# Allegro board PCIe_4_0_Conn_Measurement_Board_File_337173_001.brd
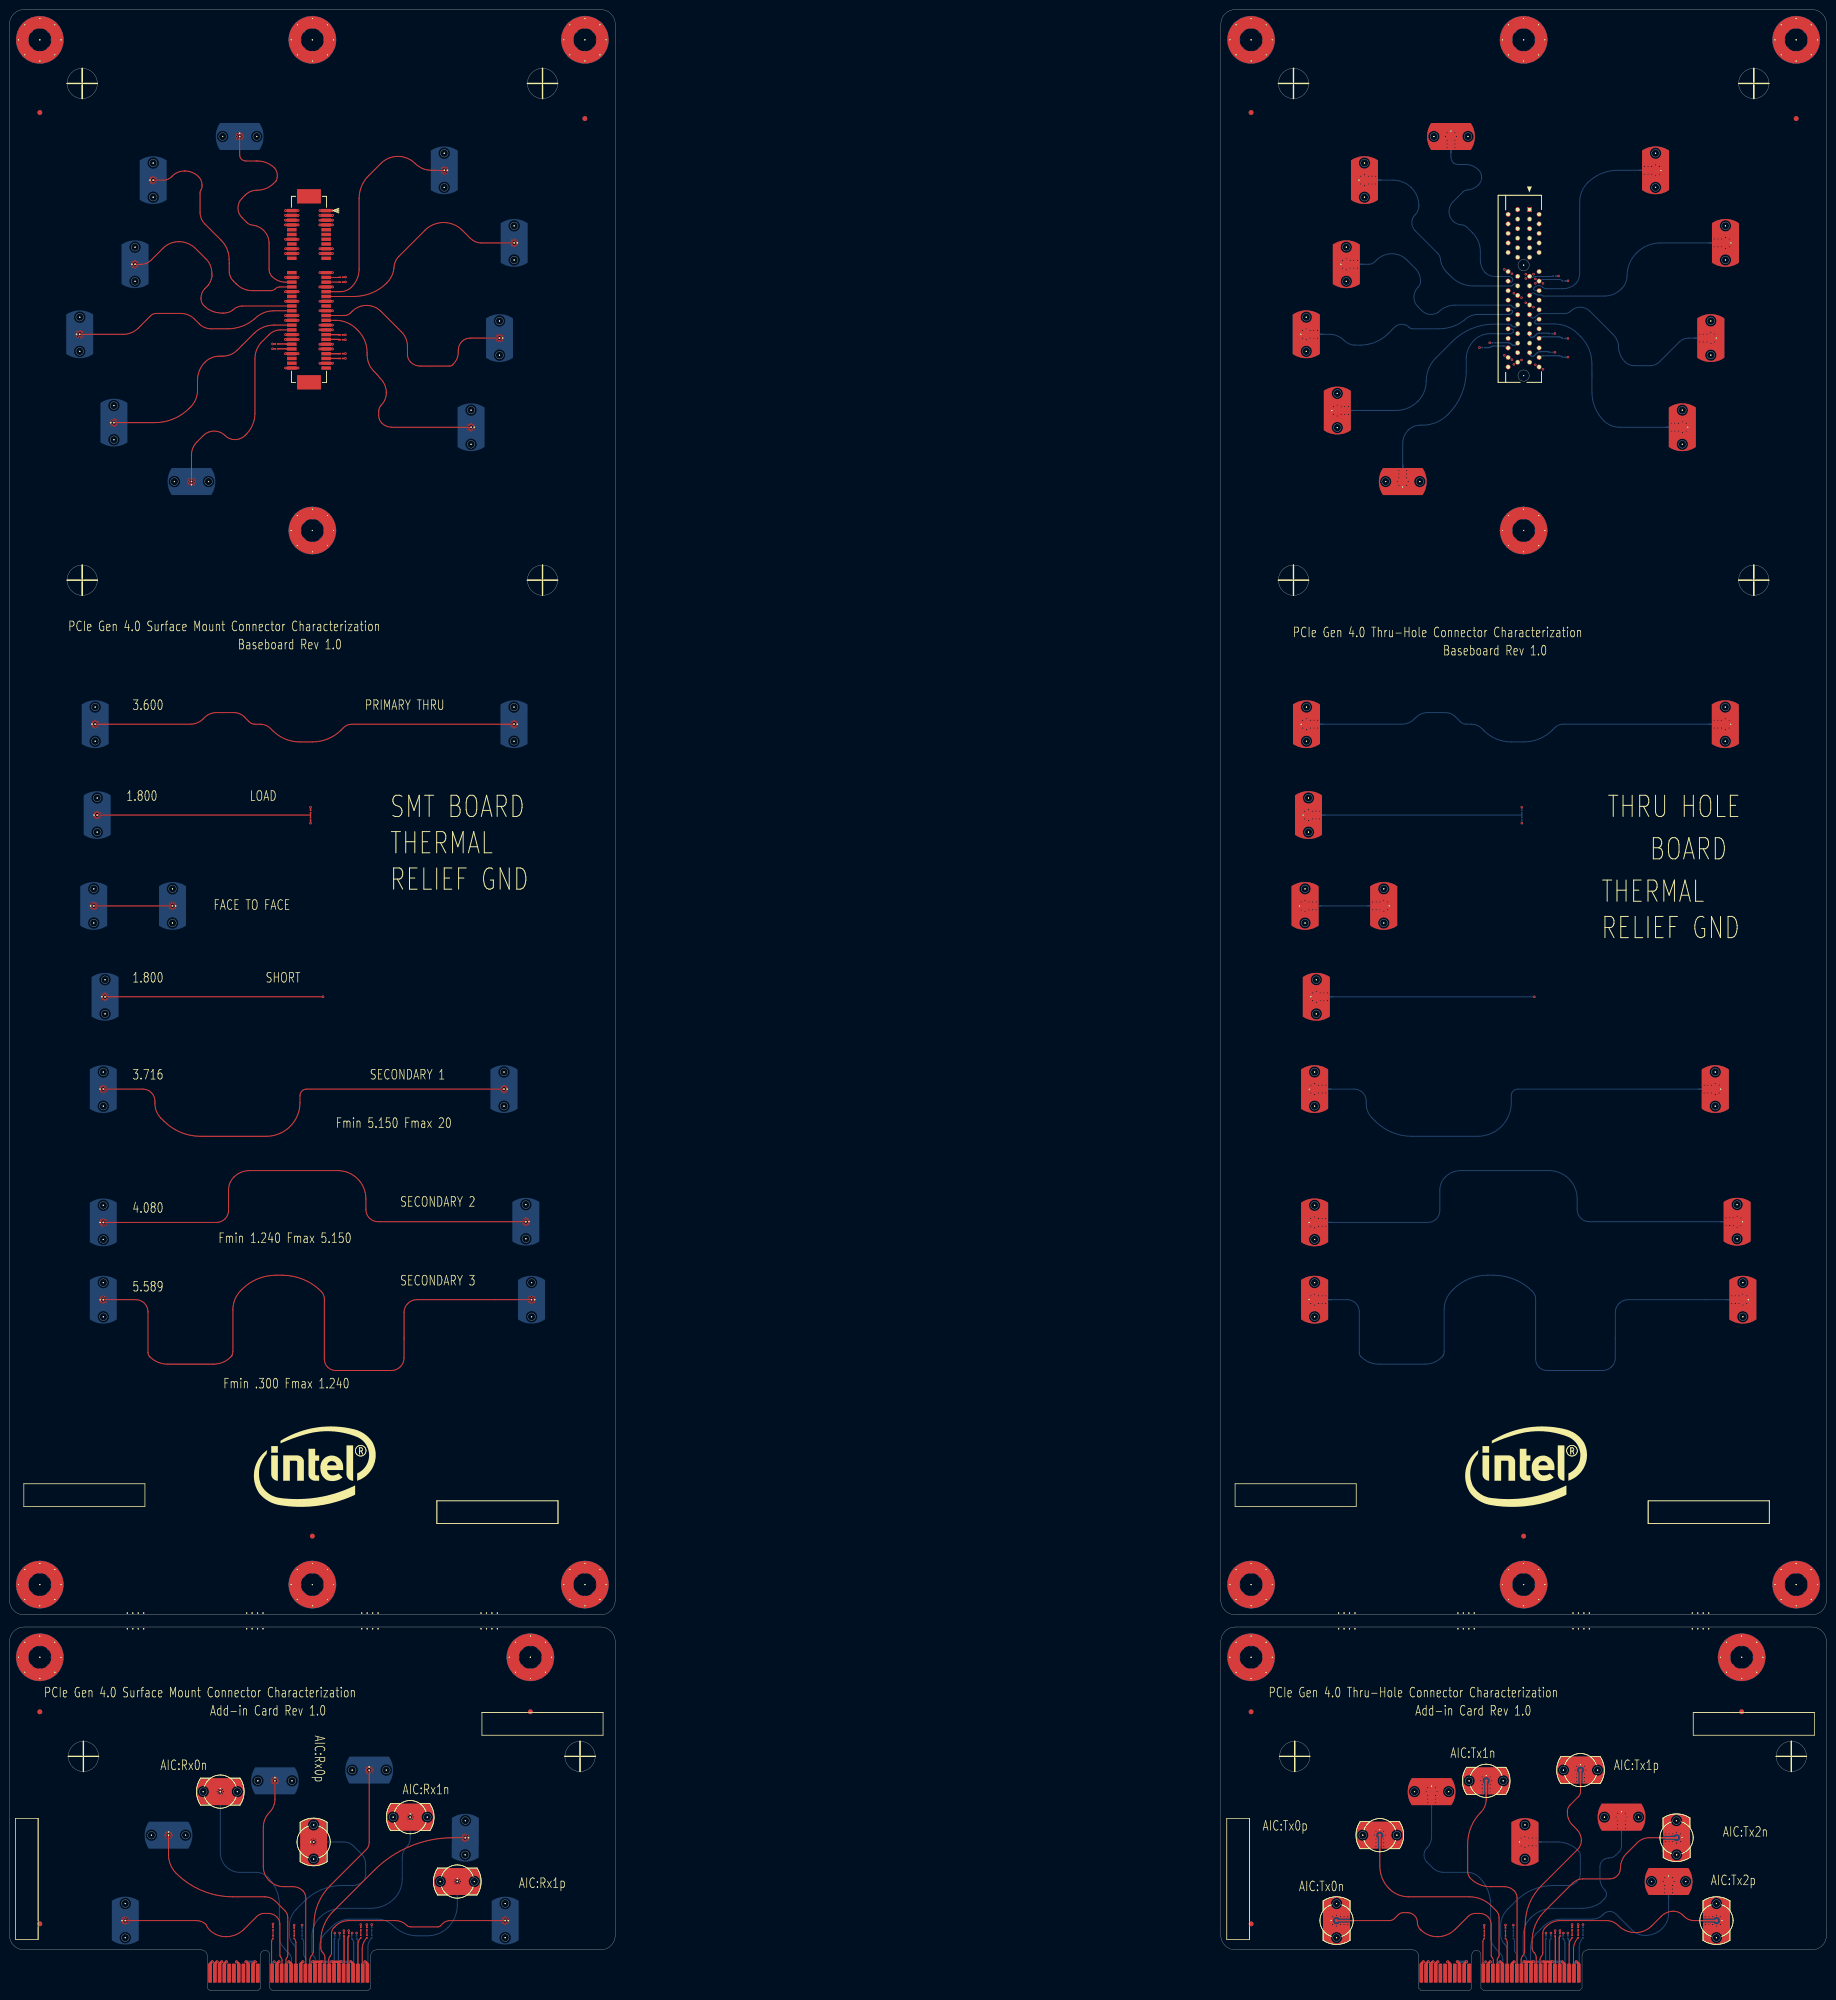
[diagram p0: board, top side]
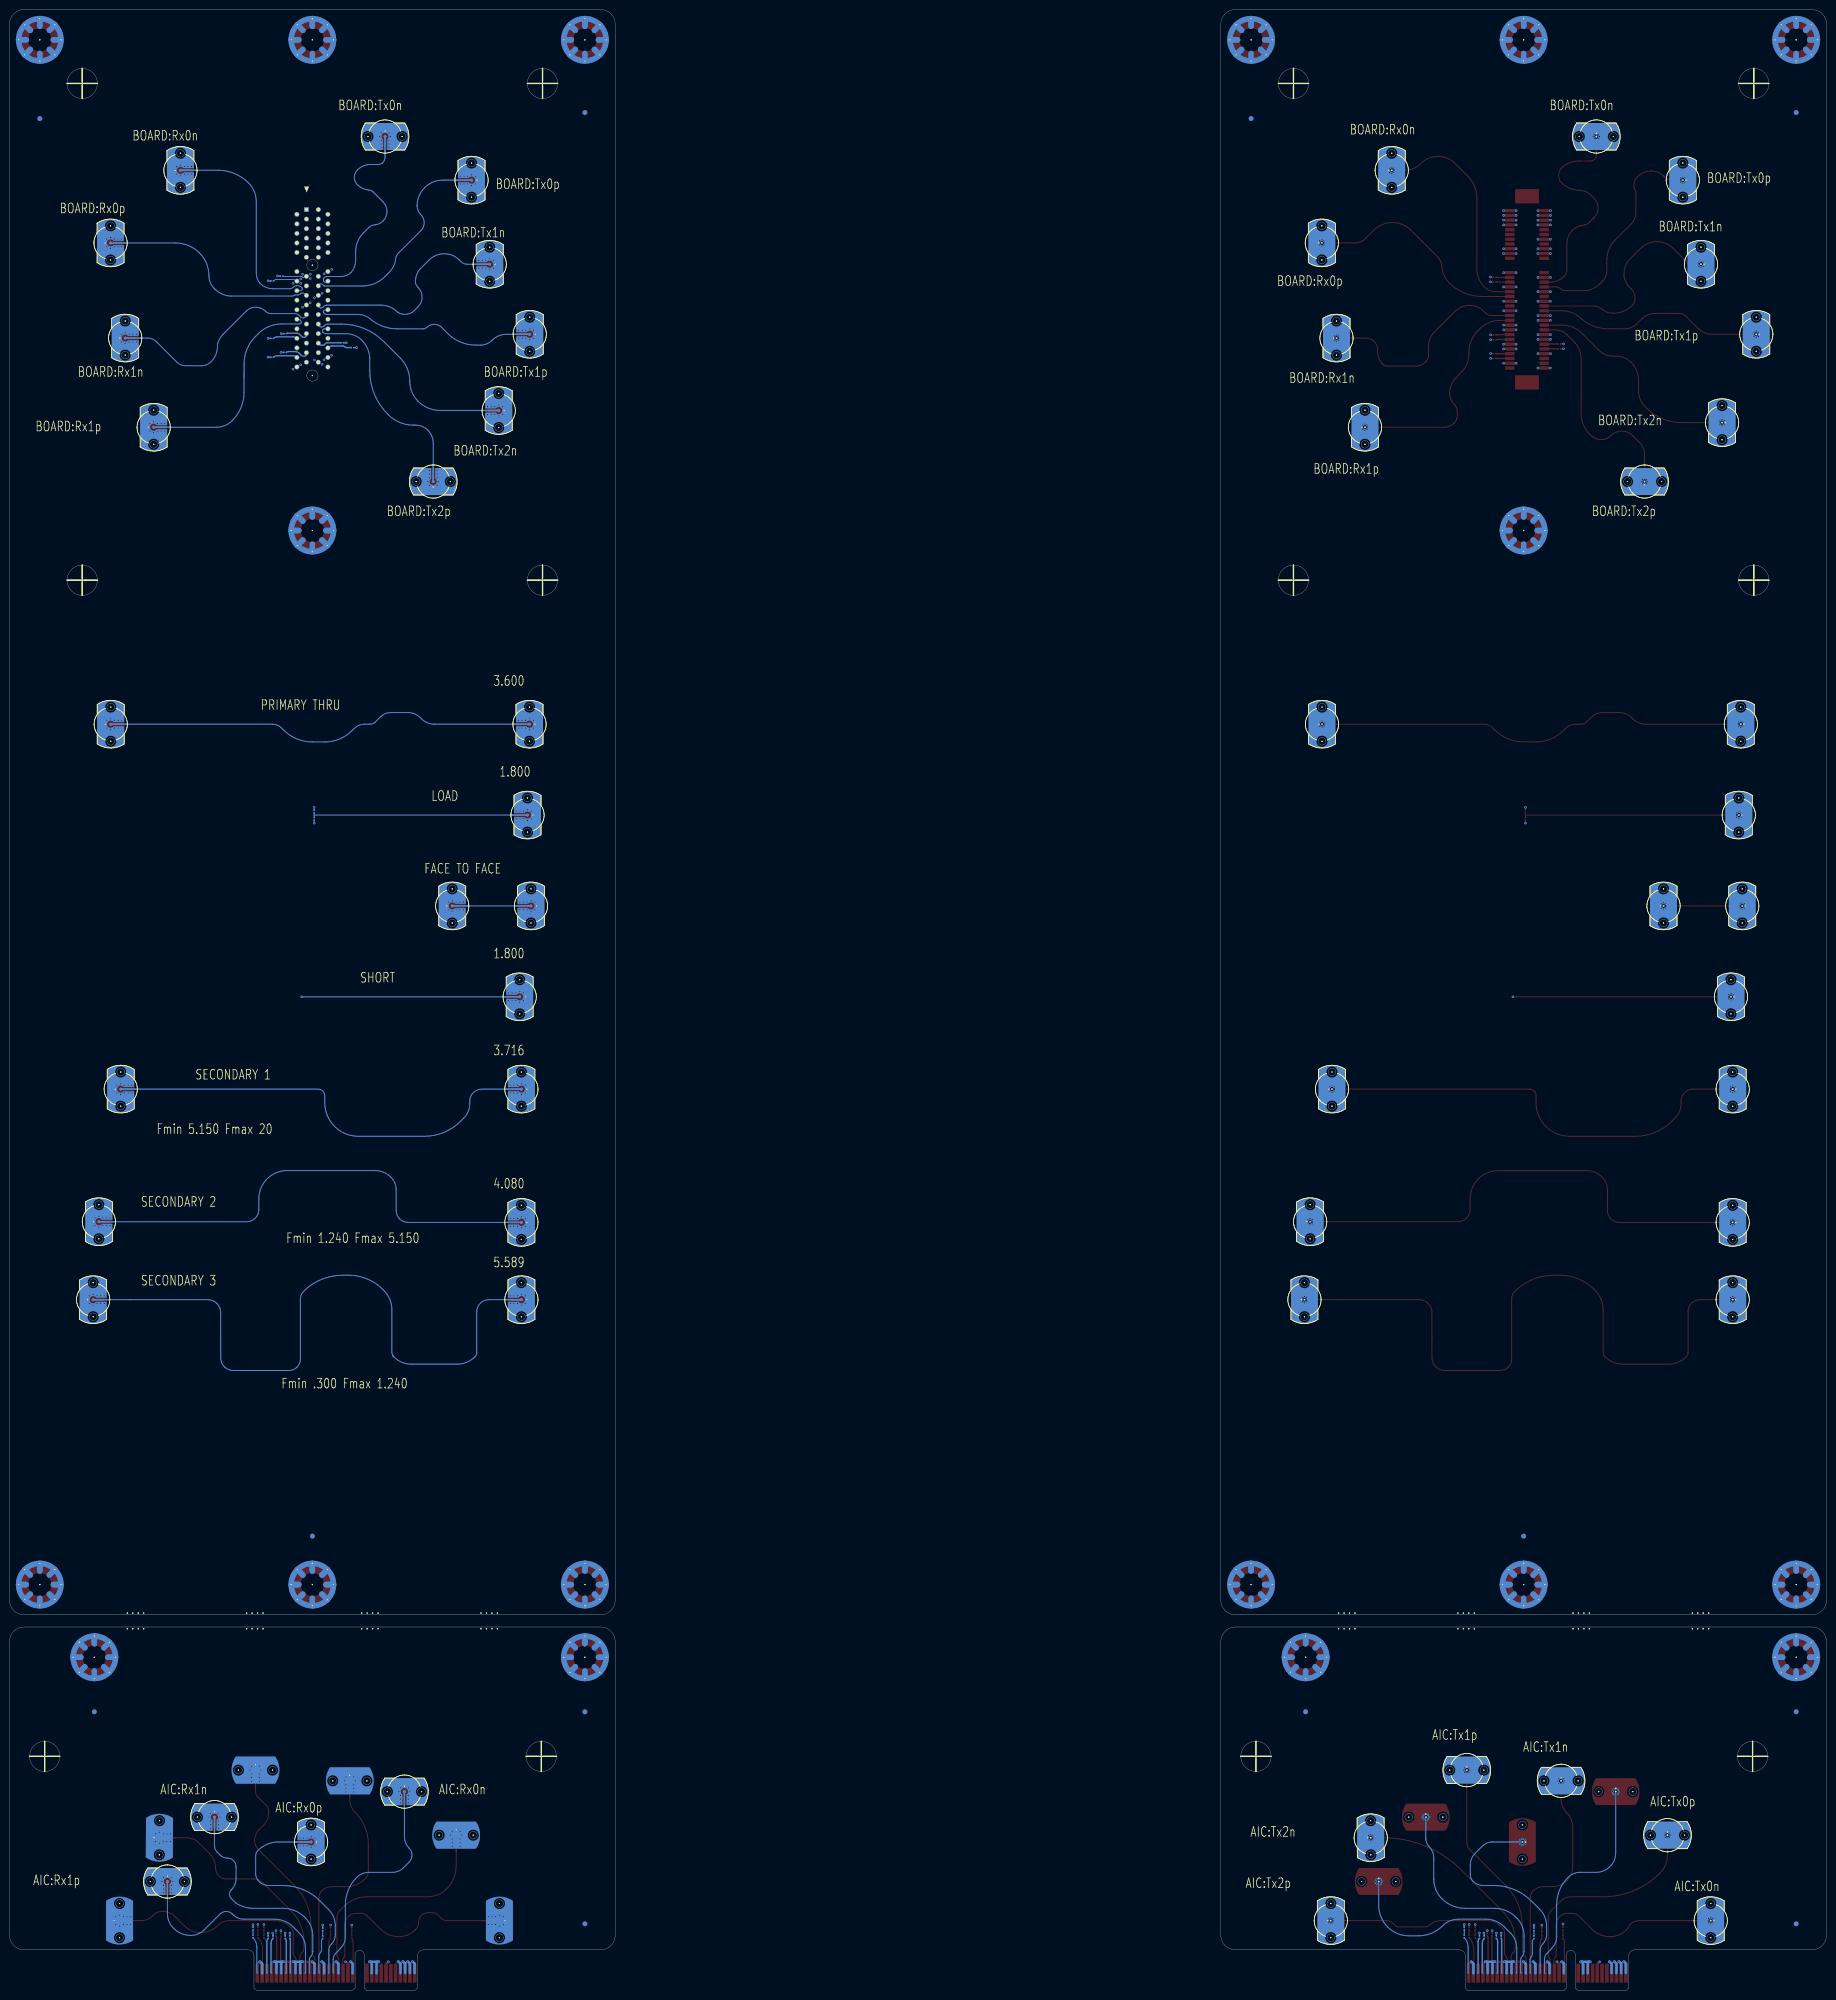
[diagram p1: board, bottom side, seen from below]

Outline 381 x 415.29 mm; copper layers: TOP, L2, L3, BOTTOM. Coordinates in mm from the lower left corner of the outline.
Outline path: 0,412.24 0,81.79 arc(0.89,79.63) 3.05,78.74 123.95,78.74 arc(126.11,79.63) 127,81.79 127,412.24 arc(126.11,414.4) 123.95,415.29 3.05,415.29 arc(0.89,414.4) 0,412.24 ; 0,73.15 0,11.56 arc(0.89,9.4) 3.05,8.51 40.18,8.51 arc(41.08,8.14) 41.45,7.24 41.45,0.51 41.96,0 52.13,0 52.64,0.51 52.64,7.45 arc(52.92,8.13) 53.59,8.41 arc(54.27,8.13) 54.55,7.45 54.55,0.51 55.05,0 75.23,0 75.74,0.51 75.74,7.24 arc(76.11,8.14) 77.01,8.51 123.95,8.51 arc(126.11,9.4) 127,11.56 127,73.15 arc(126.11,75.31) 123.95,76.2 3.05,76.2 arc(0.89,75.31) 0,73.15 ; 254,412.24 254,81.79 arc(254.89,79.63) 257.05,78.74 377.95,78.74 arc(380.11,79.63) 381,81.79 381,412.24 arc(380.11,414.4) 377.95,415.29 257.05,415.29 arc(254.89,414.4) 254,412.24 ; 254,73.15 254,11.56 arc(254.89,9.4) 257.05,8.51 294.18,8.51 arc(295.08,8.14) 295.45,7.24 295.45,0.51 295.96,0 306.13,0 306.64,0.51 306.64,7.45 arc(306.92,8.13) 307.59,8.41 arc(308.27,8.13) 308.55,7.45 308.55,0.51 309.05,0 329.23,0 329.74,0.51 329.74,7.24 arc(330.11,8.14) 331.01,8.51 377.95,8.51 arc(380.11,9.4) 381,11.56 381,73.15 arc(380.11,75.31) 377.95,76.2 257.05,76.2 arc(254.89,75.31) 254,73.15

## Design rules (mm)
nets with their own width: min track width 0.198; nets REFCLK-SMT_N REFCLK-SMT_P REFCLK-TH_N REFCLK-TH_P

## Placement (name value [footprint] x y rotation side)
C27  1.0pf  [SMC0201]  315.34 11.43 180 bottom
C28  1.0pf  [SMC0201]  329.95 11.57 180 bottom
C29  1.0pf  [SMC0201]  309.25 10.91 180 top
C30  1.0pf  [SMC0201]  313.69 10.91 180 top
C31  1.0pf  [SMC0201]  327.66 11.04 180 top
C32  1.0pf  [SMC0201]  328.93 11.04 180 top
C33  1.0pf  [SMC0201]  61.34 11.43 180 bottom
C34  1.0pf  [SMC0201]  75.95 11.57 180 bottom
C35  1.0pf  [SMC0201]  55.25 10.91 180 top
C36  1.0pf  [SMC0201]  59.69 10.91 180 top
C37  1.0pf  [SMC0201]  73.66 11.04 180 top
C38  1.0pf  [SMC0201]  74.93 11.04 180 top
J20  2.4mm, Vert, Molex SD-73387-002  [SV_MICROWAVE_SF1521-60070]  345.16 381.58 180 bottom
J44  conn64_PCIe_x4_thru_recept  [CONN64_1001873-10001MLF]  318.74 373.35 0 top
J56  2.4mm, Vert, Molex SD-73387-002  [MOLEX_SD-73252-009]  91.16 381.58 180 bottom
J60  2.4mm, Vert, Molex SD-73387-002  [MOLEX_SD-73252-009]  48.26 388.67 270 bottom
J66  conn64_PCIe_x4_smt_recept  [CONN64_SMT_1076266-101TLF]  62.79 348.14 0 top
J67  2.4mm, Vert, Molex SD-73387-002  [SV_MICROWAVE_SF1521-60070]  359.82 366.37 180 bottom
J68  2.4mm, Vert, Molex SD-73387-002  [SV_MICROWAVE_SF1521-60070]  356.75 346.42 180 bottom
J69  2.4mm, Vert, Molex SD-73387-002  [SV_MICROWAVE_SF1521-60070]  350.78 327.72 180 bottom
J70  2.4mm, Vert, Molex SD-73387-002  [SV_MICROWAVE_SF1521-60070]  302.26 388.67 270 bottom
J71  2.4mm, Vert, Molex SD-73387-002  [SV_MICROWAVE_SF1521-60070]  284.12 379.53 0 bottom
J72  2.4mm, Vert, Molex SD-73387-002  [SV_MICROWAVE_SF1521-60070]  280.32 361.89 0 bottom
J73  2.4mm, Vert, Molex SD-73387-002  [SV_MICROWAVE_SF1521-60070]  271.92 347.21 0 bottom
J74  2.4mm, Vert, Molex SD-73387-002  [SV_MICROWAVE_SF1521-60070]  278.43 331.23 0 bottom
J75  2.4mm, Vert, Molex SD-73387-002  [SV_MICROWAVE_SF1521-60070]  292.15 316.34 90 bottom
J76  2.4mm, Vert, Molex SD-73387-002  [SV_MICROWAVE_SF1521-60070]  278.27 14.65 0 top
J77  2.4mm, Vert, Molex SD-73387-002  [SV_MICROWAVE_SF1521-60070]  287.34 32.55 270 top
J78  2.4mm, Vert, Molex SD-73387-002  [SV_MICROWAVE_SF1521-60070]  309.65 43.95 270 top
J79  2.4mm, Vert, Molex SD-73387-002  [SV_MICROWAVE_SF1521-60070]  329.43 46.19 270 top
J80  2.4mm, Vert, Molex SD-73387-002  [SV_MICROWAVE_SF1521-60070]  349.57 32.02 180.4 top
J81  2.4mm, Vert, Molex SD-73387-002  [SV_MICROWAVE_SF1521-60070]  357.93 14.65 180 top
J82  2.4mm, Vert, Molex SD-73387-002  [SV_MICROWAVE_SF1521-60070]  298.19 41.69 270 bottom
J83  2.4mm, Vert, Molex SD-73387-002  [SV_MICROWAVE_SF1521-60070]  317.77 31.13 0 bottom
J84  2.4mm, Vert, Molex SD-73387-002  [SV_MICROWAVE_SF1521-60070]  338.02 36.34 270 bottom
J85  2.4mm, Vert, Molex SD-73387-002  [SV_MICROWAVE_SF1521-60070]  347.89 22.84 270 bottom
J86  2.4mm, Vert, Molex SD-73387-002  [MOLEX_SD-73252-009]  105.82 366.37 180 bottom
J87  2.4mm, Vert, Molex SD-73387-002  [MOLEX_SD-73252-009]  102.75 346.42 180 bottom
J88  2.4mm, Vert, Molex SD-73387-002  [MOLEX_SD-73252-009]  96.78 327.72 180 bottom
J89  2.4mm, Vert, Molex SD-73387-002  [MOLEX_SD-73252-009]  30.12 379.53 0 bottom
J90  2.4mm, Vert, Molex SD-73387-002  [MOLEX_SD-73252-009]  26.32 361.89 0 bottom
J91  2.4mm, Vert, Molex SD-73387-002  [MOLEX_SD-73252-009]  14.72 347.21 0 bottom
J92  2.4mm, Vert, Molex SD-73387-002  [MOLEX_SD-73252-009]  21.89 328.69 0 bottom
J93  2.4mm, Vert, Molex SD-73387-002  [MOLEX_SD-73252-009]  38.15 316.34 90 bottom
J94  2.4mm, Vert, Molex SD-73387-002  [MOLEX_SD-73252-009]  24.27 14.65 0 bottom
J95  2.4mm, Vert, Molex SD-73387-002  [MOLEX_SD-73252-009]  33.34 32.55 270 bottom
J96  2.4mm, Vert, Molex SD-73387-002  [MOLEX_SD-73252-009]  55.65 43.95 270 bottom
J97  2.4mm, Vert, Molex SD-73387-002  [MOLEX_SD-73252-009]  75.43 46.19 270 bottom
J98  2.4mm, Vert, Molex SD-73387-002  [MOLEX_SD-73252-009]  95.57 32.02 179.6 bottom
J99  2.4mm, Vert, Molex SD-73387-002  [MOLEX_SD-73252-009]  103.93 14.65 180 bottom
J100  2.4mm, Vert, Molex SD-73387-002  [MOLEX_SD-73252-009]  44.19 41.69 270 top
J101  2.4mm, Vert, Molex SD-73387-002  [MOLEX_SD-73252-009]  63.77 31.13 0 top
J102  2.4mm, Vert, Molex SD-73387-002  [MOLEX_SD-73252-009]  84.02 36.34 270 top
J103  2.4mm, Vert, Molex SD-73387-002  [MOLEX_SD-73252-009]  93.89 22.84 270 top
J104  2.4mm, Vert, Molex SD-73387-002  [MOLEX_SD-73252-009]  17.96 265.47 0 bottom
J105  2.4mm, Vert, Molex SD-73387-002  [MOLEX_SD-73252-009]  18.39 246.42 0 bottom
J106  2.4mm, Vert, Molex SD-73387-002  [MOLEX_SD-73252-009]  17.66 227.37 0 bottom
J107  2.4mm, Vert, Molex SD-73387-002  [MOLEX_SD-73252-009]  20.03 208.32 0 bottom
J108  2.4mm, Vert, Molex SD-73387-002  [MOLEX_SD-73252-009]  19.66 188.96 0 bottom
J109  2.4mm, Vert, Molex SD-73387-002  [MOLEX_SD-73252-009]  19.66 161.02 0 bottom
J110  2.4mm, Vert, Molex SD-73387-002  [MOLEX_SD-73252-009]  19.66 144.82 0 bottom
J111  2.4mm, Vert, Molex SD-73387-002  [MOLEX_SD-73252-009]  105.78 265.47 180 bottom
J112  2.4mm, Vert, Molex SD-73387-002  [MOLEX_SD-73252-009]  34.17 227.37 180 bottom
J113  2.4mm, Vert, Molex SD-73387-002  [MOLEX_SD-73252-009]  103.69 188.96 180 bottom
J114  2.4mm, Vert, Molex SD-73387-002  [MOLEX_SD-73252-009]  108.27 161.17 180 bottom
J115  2.4mm, Vert, Molex SD-73387-002  [MOLEX_SD-73252-009]  109.46 144.82 180 bottom
J116  2.4mm, Vert, Molex SD-73387-002  [SV_MICROWAVE_SF1521-60070]  271.96 265.47 0 bottom
J117  2.4mm, Vert, Molex SD-73387-002  [SV_MICROWAVE_SF1521-60070]  272.39 246.42 0 bottom
J118  2.4mm, Vert, Molex SD-73387-002  [SV_MICROWAVE_SF1521-60070]  271.66 227.37 0 bottom
J119  2.4mm, Vert, Molex SD-73387-002  [SV_MICROWAVE_SF1521-60070]  274.03 208.32 0 bottom
J120  2.4mm, Vert, Molex SD-73387-002  [SV_MICROWAVE_SF1521-60070]  273.66 188.96 0 bottom
J121  2.4mm, Vert, Molex SD-73387-002  [SV_MICROWAVE_SF1521-60070]  273.66 161.02 0 bottom
J122  2.4mm, Vert, Molex SD-73387-002  [SV_MICROWAVE_SF1521-60070]  273.66 144.82 0 bottom
J123  2.4mm, Vert, Molex SD-73387-002  [SV_MICROWAVE_SF1521-60070]  359.78 265.47 180 bottom
J124  2.4mm, Vert, Molex SD-73387-002  [SV_MICROWAVE_SF1521-60070]  288.17 227.37 180 bottom
J125  2.4mm, Vert, Molex SD-73387-002  [SV_MICROWAVE_SF1521-60070]  357.69 188.96 180 bottom
J126  2.4mm, Vert, Molex SD-73387-002  [SV_MICROWAVE_SF1521-60070]  362.27 161.17 180 bottom
J127  2.4mm, Vert, Molex SD-73387-002  [SV_MICROWAVE_SF1521-60070]  363.46 144.82 180 bottom
NOREF  -  []  381 11.56 0 top
NOREF#2  -  []  41.16 8.06 0 top
NOREF#3  -  []  6.35 85.09 0 top
NOREF#4  -  []  381.13 58.7 0 top
NOREF#5  -  []  -50.39 413.32 7 top
NOREF#6  -  [unnamed#2]  269.24 399.8 0 top
NOREF#7  -  []  325.12 80.01 0 top
NOREF#8  -  []  431.43 -9.98 0 top
NOREF#9  -  []  40.46 0.93 0 top
NOREF#10  -  [unnamed#2]  317.5 95.25 0 top
NOREF#11  -  []  405.42 469.29 277 top
NOREF#12  -  []  378.99 398.49 0 top
NOREF#13  -  [unnamed#2]  365.76 295.66 0 top
NOREF#14  -  []  403.95 -73.03 0 top
NOREF#15  -  []  329.74 0.51 0 top
NOREF#16  -  [unnamed#2]  119.63 49.07 0 top
NOREF#17  -  [unnamed#2]  120.65 392.43 0 top
NOREF#18  -  []  254 11.56 0 top
NOREF#19  -  []  -279.16 357.38 270 top
NOREF#20  -  []  126.38 414.08 0 top
NOREF#21  -  []  54.55 0.51 0 top
NOREF#22  -  []  -258.65 -67.84 0 top
NOREF#23  -  []  329.43 547.83 0 top
NOREF#24  -  []  2.93 106.51 0 top
NOREF#25  -  []  6.35 85.09 0 top
NOREF#26  -  [unnamed#3]  63.5 408.94 0 top
NOREF#27  -  []  0 11.56 0 top
NOREF#28  -  []  280.42 77.47 0 top
NOREF#29  -  [unnamed#3]  260.35 69.85 0 top
NOREF#30  -  [unnamed#2]  373.63 49.07 0 top
NOREF#31  -  []  343.61 97.89 0 top
NOREF#32  -  []  419.28 -16.92 0 top
NOREF#33  -  [unnamed#3]  63.5 85.09 0 top
NOREF#34  -  [unnamed#2]  15.24 399.8 0 top
NOREF#35  -  []  354.58 77.47 0 top
NOREF#36  -  [unnamed#3]  120.65 408.94 0 top
NOREF#37  -  [unnamed#3]  63.5 306.07 0 top
NOREF#38  -  []  127 407.67 0 top
NOREF#39  -  [unnamed#3]  6.35 85.09 0 top
NOREF#40  -  []  53.34 80.01 0 top
NOREF#41  -  []  318.01 109.75 0 top
NOREF#42  -  []  845.26 89.87 0 top
NOREF#43  -  []  41.1 4.29 0 top
NOREF#44  -  [unnamed#2]  365.76 399.8 0 top
NOREF#45  -  []  89.61 97.89 0 top
NOREF#46  -  []  453.55 -17.32 0 top
NOREF#47  -  []  429.69 75.67 0 top
NOREF#48  -  []  350.52 80.01 0 top
NOREF#49  -  []  3.05 76.2 0 top
NOREF#50  -  []  650.88 198.37 0 top
NOREF#51  -  [unnamed#2]  15.49 49.07 0 top
NOREF#52  -  []  305.44 77.47 0 top
NOREF#53  -  []  306.64 0.51 0 top
NOREF#54  -  []  75.74 0.51 0 top
NOREF#55  -  [unnamed#3]  6.35 69.85 0 top
NOREF#56  -  []  308.55 0.51 0 top
NOREF#57  -  []  127 11.56 0 top
NOREF#58  -  []  -111.23 120.93 0 top
NOREF#59  -  []  26.42 77.47 0 top
NOREF#60  -  []  51.44 77.47 0 top
NOREF#61  -  []  403.89 -29.7 0 top
NOREF#62  -  []  662.31 185.42 0 top
NOREF#63  -  []  276.86 80.01 0 top
NOREF#64  -  [unnamed#2]  260.35 393.7 0 top
NOREF#65  -  []  504.83 -5.87 0 top
NOREF#66  -  []  380.88 -8.92 0 top
NOREF#67  -  [unnamed#3]  120.65 85.09 0 top
NOREF#68  -  [unnamed#2]  109.22 58.42 0 top
NOREF#69  -  []  -64.46 384.41 0 top
NOREF#70  -  []  377.83 -5.87 0 top
NOREF#71  -  []  75.56 77.47 0 top
NOREF#72  -  [unnamed#3]  317.5 85.09 0 top
NOREF#73  -  []  432.34 -17.22 0 top
NOREF#74  -  []  453.07 -17.43 0 top
NOREF#75  -  []  419.92 -13.56 0 top
NOREF#76  -  []  410.64 75.67 0 top
NOREF#77  -  []  41.45 0.51 0 top
NOREF#78  -  []  41.96 0 0 top
NOREF#79  -  []  430.47 -16.92 0 top
NOREF#80  -  []  52.64 0.51 0 top
NOREF#81  -  [unnamed#2]  260.35 58.42 0 top
NOREF#82  -  [unnamed#2]  111.76 295.66 0 top
NOREF#83  -  [unnamed#2]  260.35 13.97 0 top
NOREF#84  -  [unnamed#2]  269.49 49.07 0 top
NOREF#85  -  []  403.95 -6.46 0 top
NOREF#86  -  [unnamed#2]  63.5 95.25 0 top
NOREF#87  -  [unnamed#3]  363.22 69.85 0 top
NOREF#88  -  []  339 -6.46 0 top
NOREF#89  -  [unnamed#2]  111.76 399.8 0 top
NOREF#90  -  []  670.56 186.06 0 top
NOREF#91  -  []  378.78 398.25 0 top
NOREF#92  -  [unnamed#2]  363.22 58.42 0 top
NOREF#93  -  [unnamed#2]  374.65 392.43 0 top
NOREF#94  -  []  300.99 80.01 0 top
NOREF#95  -  [unnamed#3]  317.5 408.94 0 top
NOREF#96  -  [unnamed#3]  260.35 85.09 0 top
NOREF#97  -  []  651.76 189.31 0 top
NOREF#98  -  [unnamed#2]  269.24 295.66 0 top
NOREF#99  -  [unnamed#3]  374.65 408.94 0 top
NOREF#100  -  []  1.32 35.89 0 top
NOREF#101  -  []  3.05 415.29 0 top
NOREF#102  -  [unnamed#3]  317.5 306.07 0 top
NOREF#103  -  []  382.7 28.68 0 top
NOREF#104  -  [unnamed#2]  6.35 58.42 0 top
NOREF#105  -  []  268.86 36.17 0 top
NOREF#106  -  []  -110.54 70.33 0 top
NOREF#107  -  [unnamed#2]  6.35 13.97 0 top
NOREF#108  -  []  295.45 0.51 0 top
NOREF#109  -  []  3.05 8.51 0 top
NOREF#110  -  []  272.21 43.92 0 top
NOREF#111  -  []  329.56 77.47 0 top
NOREF#112  -  []  -255.09 -81.65 0 top
NOREF#113  -  [unnamed#3]  260.35 408.94 0 top
NOREF#114  -  []  3.05 78.74 0 top
NOREF#115  -  [unnamed#3]  6.35 408.94 0 top
NOREF#116  -  []  102.87 81.28 0 top
NOREF#117  -  []  77.47 80.01 0 top
NOREF#118  -  [unnamed#3]  109.22 69.85 0 top
NOREF#119  -  []  270 114.35 0 top
NOREF#120  -  [unnamed#2]  6.35 393.7 0 top
NOREF#121  -  [unnamed#3]  374.65 85.09 0 top
NOREF#122  -  []  650.88 198.37 0 top
NOREF#123  -  []  64.01 109.75 0 top
NOREF#124  -  [unnamed#2]  15.24 295.66 0 top
NOREF#125  -  []  100.58 77.47 0 top
NOREF#126  -  []  27.94 80.01 0 top
NOREF#127  -  [unnamed#4]  280.42 77.47 0 bottom
NOREF#128  -  [unnamed#2]  63.5 95.25 180 bottom
NOREF#129  -  [unnamed#2]  260.35 58.42 180 bottom
NOREF#130  -  [unnamed#4]  26.42 77.47 0 bottom
NOREF#131  -  [unnamed#4]  280.42 77.47 180 bottom
NOREF#132  -  [unnamed#4]  51.44 77.47 180 bottom
NOREF#133  -  [unnamed#2]  120.65 392.43 180 bottom
NOREF#134  -  [unnamed#4]  75.56 77.47 180 bottom
NOREF#135  -  [unnamed#2]  6.35 393.7 180 bottom
NOREF#136  -  [unnamed#4]  100.58 77.47 180 bottom
NOREF#137  -  [unnamed#4]  354.58 77.47 0 bottom
NOREF#138  -  [unnamed#2]  109.22 58.42 180 bottom
NOREF#139  -  [unnamed#2]  260.35 393.7 180 bottom
NOREF#140  -  [unnamed#2]  6.35 58.42 180 bottom
NOREF#141  -  [unnamed#4]  51.44 77.47 0 bottom
NOREF#142  -  [unnamed#4]  329.56 77.47 0 bottom
NOREF#143  -  [unnamed#2]  260.35 13.97 180 bottom
NOREF#144  -  [unnamed#4]  354.58 77.47 180 bottom
NOREF#145  -  [unnamed#2]  374.65 392.43 180 bottom
NOREF#146  -  [unnamed#4]  305.44 77.47 180 bottom
NOREF#147  -  [unnamed#4]  75.56 77.47 0 bottom
NOREF#148  -  [unnamed#2]  363.22 58.42 180 bottom
NOREF#149  -  [unnamed#4]  329.56 77.47 180 bottom
NOREF#150  -  [unnamed#2]  317.5 95.25 180 bottom
NOREF#151  -  [unnamed#4]  100.58 77.47 0 bottom
NOREF#152  -  [unnamed#4]  26.42 77.47 180 bottom
NOREF#153  -  [unnamed#2]  6.35 13.97 180 bottom
NOREF#154  -  [unnamed#4]  305.44 77.47 0 bottom
P1  conn64_PCIe_x4_gold_fingers  [3GIO_X4_GF]  42.05 3.49 0 top
P2  conn64_PCIe_x4_gold_fingers  [3GIO_X4_GF]  296.05 3.49 0 top
R22  43ohm  [SMR0201]  310.98 345.44 270 bottom
R23  43ohm  [SMR0201]  308.83 344.42 270 bottom
R27  43ohm  [SMR0201]  325.67 346.33 270 bottom
R28  43ohm  [SMR0201]  322.92 347.35 270 bottom
R29  43ohm  [SMR0201]  322.95 343.41 270 bottom
R30  43ohm  [SMR0201]  325.67 342.39 270 bottom
R32  43ohm  [SMR0201]  309.25 13.09 0 top
R33  43ohm  [SMR0201]  313.69 13.09 0 top
R34  43ohm  [SMR0201]  324.1 11.95 0 top
R35  43ohm  [SMR0201]  325.12 11.95 0 top
R36  43ohm  [SMR0201]  327.66 13.22 0 top
R37  43ohm  [SMR0201]  328.93 13.22 0 top
R38  43ohm  [SMR0201]  315.34 12.56 0 bottom
R39  43ohm  [SMR0201]  323.22 10.91 0 bottom
R40  43ohm  [SMR0201]  322.2 10.91 0 bottom
R41  43ohm  [SMR0201]  325.75 10.91 0 bottom
R42  43ohm  [SMR0201]  326.77 10.91 0 bottom
R43  43ohm  [SMR0201]  329.95 12.69 0 bottom
R44  43ohm  [SMR0201]  55.25 13.22 0 top
R45  43ohm  [SMR0201]  59.69 13.09 0 top
R46  43ohm  [SMR0201]  70.1 11.95 0 top
R47  43ohm  [SMR0201]  71.12 11.95 0 top
R48  43ohm  [SMR0201]  73.66 13.22 0 top
R49  43ohm  [SMR0201]  74.93 13.22 0 top
R50  43ohm  [SMR0201]  61.34 12.56 0 bottom
R51  43ohm  [SMR0201]  69.22 10.91 0 bottom
R52  43ohm  [SMR0201]  68.2 10.91 0 bottom
R53  43ohm  [SMR0201]  71.75 10.91 0 bottom
R54  43ohm  [SMR0201]  72.77 10.91 0 bottom
R55  43ohm  [SMR0201]  75.95 12.69 0 bottom
R56  43ohm  [SMR0201]  55.74 345.19 90 top
R57  43ohm  [SMR0201]  55.74 344.17 90 top
R58  43ohm  [SMR0201]  69.3 346.08 90 top
R59  43ohm  [SMR0201]  69.3 347.09 90 top
R60  43ohm  [SMR0201]  69.3 343.15 90 top
R61  43ohm  [SMR0201]  69.3 342.14 90 top
R62  50ohm  [SMR0201]  323.68 359.41 270 bottom
R63  50ohm  [SMR0201]  325.67 358.39 270 bottom
R64  50ohm  [SMR0201]  69.33 359.16 90 top
R65  50ohm  [SMR0201]  69.33 358.14 90 top
R66  50ohm  [SMR0201]  63.12 247.41 0 top
R67  50ohm  [SMR0201]  63.12 245.35 180 top
R68  50ohm  [SMR0201]  317.12 247.41 180 bottom
R69  50ohm  [SMR0201]  317.12 245.35 0 bottom

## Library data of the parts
C27-C38 = CAP NP
J20 J56 J60 J67-J127 = 2.4mm, Vert, Molex SD-73387-002
J44 = conn64_PCIe_x4_thru_recept
J66 = conn64_PCIe_x4_smt_recept
P1 P2 = conn64_PCIe_x4_gold_fingers
R22 R23 R27-R30 R32-R69 = RESISTOR

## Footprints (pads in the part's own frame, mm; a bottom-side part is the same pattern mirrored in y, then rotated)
3GIO_X4_GF
  rect 0.7x3.91 smd: A1(0,0.14) A2(1,0.14) A3(2,0.14) A4(3,0.14) A5(4,0.14) A6(5,0.14) A7(6,0.14) A8(7,0.14) A9(8,0.14) A10(9,0.14) A11(10,0.14) A12(13,0.14) A13(14,0.14) A14(15,0.14) A15(16,0.14) A16(17,0.14) A17(18,0.14) A18(19,0.14) A19(20,0.14) A20(21,0.14) A21(22,0.14) A22(23,0.14) A23(24,0.14) A24(25,0.14) A25(26,0.14) A26(27,0.14) A27(28,0.14) A28(29,0.14) A29(30,0.14) A30(31,0.14) A31(32,0.14) A32(33,0.14) B1(0,0.14) B2(1,0.14) B3(2,0.14) B4(3,0.14) B5(4,0.14) B6(5,0.14) B7(6,0.14) B8(7,0.14) B9(8,0.14) B10(9,0.14) B11(10,0.14) B12(13,0.14) B13(14,0.14) B14(15,0.14) B15(16,0.14) B16(17,0.14) B17(18,0.14) B18(19,0.14) B19(20,0.14) B20(21,0.14) B21(22,0.14) B22(23,0.14) B23(24,0.14) B24(25,0.14) B25(26,0.14) B26(27,0.14) B27(28,0.14) B28(29,0.14) B29(30,0.14) B30(31,0.14) B31(32,0.14) B32(33,0.14)
CONN64_1001873-10001MLF
  round 0.254 hole 2.362 unplated: (-1.25,-11.65) (-1.25,-34.8)
  rect 1.016x1.016 hole 0.711: A1(0,0)
  round 1.016 hole 0.749: A2(2,-1) A3(0,-2) A4(2,-3) A5(0,-4) A6(2,-5) A7(0,-6) A8(2,-7) A9(0,-8) A10(2,-9) A11(0,-10) A12(2,-13) A13(0,-14) A14(2,-15) A15(0,-16) A16(2,-17) A17(0,-18) A18(2,-19) A19(0,-20) A20(2,-21) A21(0,-22) A22(2,-23) A23(0,-24) A24(2,-25) A25(0,-26) A26(2,-27) A27(0,-28) A28(2,-29) A29(0,-30) A30(2,-31) A31(0,-32) A32(2,-33) B1(-2.5,0) B2(-4.5,-1) B3(-2.5,-2) B4(-4.5,-3) B5(-2.5,-4) B6(-4.5,-5) B7(-2.5,-6) B8(-4.5,-7) B9(-2.5,-8) B10(-4.5,-9) B11(-2.5,-10) B12(-4.5,-13) B13(-2.5,-14) B14(-4.5,-15) B15(-2.5,-16) B16(-4.5,-17) B17(-2.5,-18) B18(-4.5,-19) B19(-2.5,-20) B20(-4.5,-21) B21(-2.5,-22) B22(-4.5,-23) B23(-2.5,-24) B24(-4.5,-25) B25(-2.5,-26) B26(-4.5,-27) B27(-2.5,-28) B28(-4.5,-29) B29(-2.5,-30) B30(-4.5,-31) B31(-2.5,-32) B32(-4.5,-33)
CONN64_SMT_1076266-101TLF
  rect 5x3 smd: (0,28) (0,-11)
  rect 2x0.7 smd: A1(3.6,25) A2(3.6,24) A3(3.6,23) A4(3.6,22) A5(3.6,21) A6(3.6,20) A7(3.6,19) A8(3.6,18) A9(3.6,17) A10(3.6,16) A11(3.6,15) A12(3.6,12) A13(3.6,11) A14(3.6,10) A15(3.6,9) A16(3.6,8) A17(3.6,7) A18(3.6,6) A19(3.6,5) A20(3.6,4) A21(3.6,3) A22(3.6,2) A23(3.6,1) A24(3.6,0) A25(3.6,-1) A26(3.6,-2) A27(3.6,-3) A28(3.6,-4) A29(3.6,-5) A30(3.6,-6) A31(3.6,-7) A32(3.6,-8) B1(-3.6,25) B2(-3.6,24) B3(-3.6,23) B4(-3.6,22) B5(-3.6,21) B6(-3.6,20) B7(-3.6,19) B8(-3.6,18) B9(-3.6,17) B10(-3.6,16) B11(-3.6,15) B12(-3.6,12) B13(-3.6,11) B14(-3.6,10) B15(-3.6,9) B16(-3.6,8) B17(-3.6,7) B18(-3.6,6) B19(-3.6,5) B20(-3.6,4) B21(-3.6,3) B22(-3.6,2) B23(-3.6,1) B24(-3.6,0) B25(-3.6,-1) B26(-3.6,-2) B27(-3.6,-3) B28(-3.6,-4) B29(-3.6,-5) B30(-3.6,-6) B31(-3.6,-7) B32(-3.6,-8)
MOLEX_SD-73252-009
  round 0.254 hole 1.6 unplated: (0,3.579) (0,-3.579)
  round 0.457 hole 0.254: 1(0,0) 2(-0.66,0)
SMC0201
  custom 0.076x0.076 smd: 1(0,0) 2(0,-0.533)
SMR0201
  custom 0.076x0.076 smd: 1(0,0) 2(0,-0.533)
SV_MICROWAVE_SF1521-60070
  round 0.254 hole 1.6 unplated: (0,3.579) (0,-3.579)
  round 0.508 smd: 1(0,0)
  round 0.508 hole 0.254: 2(-1.141,0)
unnamed#2
  round 0.254 hole 6.35 unplated: (0,0)
unnamed#3
  round 0.254 hole 3.962 unplated: (0,0)
  round 0.508 hole 0.254: 1(0,4.445) 2(3.15,3.15) 3(4.445,0) 4(3.15,-3.15) 5(0,-4.445) 6(-3.15,-3.15) 7(-4.445,0) 8(-3.15,3.15)
unnamed#4
  round 0.254 hole 0.635 unplated: (-1.714,1.651) (-0.572,1.651) (0.572,1.651) (1.714,1.651)

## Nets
GND: J56.2(GND) J60.2(GND) J66.A1(PRESENT) J66.A2(V12-A2) J66.A3(V12-A3) J66.A4(GND-A4) J66.A9(V3.3-A9) J66.A10(V3.3-A10) J66.A12(GND-A12) J66.A15(GND-A15) J66.A18(GND-A18) J66.A20(GND-A20) J66.A23(GND-A23) J66.A24(GND-A24) J66.A27(GND-A27) J66.A28(GND-A28) J66.A31(GND-A31) J66.B1(V12-B1) J66.B2(V12-B2) J66.B3(V12-B3) J66.B4(GND-B4) J66.B7(GND-B7) J66.B9(JTAG-B9) J66.B10(V3.3-B10) J66.B13(GND-B13) J66.B16(GND-B16) J66.B18(GND-B18) J66.B21(GND-B21) J66.B22(GND-B22) J66.B25(GND-B25) J66.B26(GND-B26) J66.B29(GND-B29) J66.B32(GND-B32) J86.2(GND) J87.2(GND) J88.2(GND) J89.2(GND) J90.2(GND) J91.2(GND) J92.2(GND) J93.2(GND) J104.2(GND) J105.2(GND) J106.2(GND) J107.1(SIGNAL) J107.2(GND) J108.2(GND) J109.2(GND) J110.2(GND) J111.2(GND) J112.2(GND) J113.2(GND) J114.2(GND) J115.2(GND) R56.1 R57.1 R58.2 R59.2 R60.2 R61.2 R64.2 R65.2 R66.1 R67.1
GND1: J20.2(GND) J44.A1(PRESENT) J44.A2(V12-A2) J44.A3(V12-A3) J44.A4(GND-A4) J44.A9(V3.3-A9) J44.A10(V3.3-A10) J44.A12(GND-A12) J44.A15(GND-A15) J44.A18(GND-A18) J44.A20(GND-A20) J44.A23(GND-A23) J44.A24(GND-A24) J44.A27(GND-A27) J44.A28(GND-A28) J44.A31(GND-A31) J44.B1(V12-B1) J44.B2(V12-B2) J44.B3(V12-B3) J44.B4(GND-B4) J44.B7(GND-B7) J44.B9(JTAG-B9) J44.B10(V3.3-B10) J44.B13(GND-B13) J44.B16(GND-B16) J44.B18(GND-B18) J44.B21(GND-B21) J44.B22(GND-B22) J44.B25(GND-B25) J44.B26(GND-B26) J44.B29(GND-B29) J44.B32(GND-B32) J67.2(GND) J68.2(GND) J69.2(GND) J70.2(GND) J71.2(GND) J72.2(GND) J73.2(GND) J74.2(GND) J75.2(GND) J116.2(GND) J117.2(GND) J118.2(GND) J119.1(SIGNAL) J119.2(GND) J120.2(GND) J121.2(GND) J122.2(GND) J123.2(GND) J124.2(GND) J125.2(GND) J126.2(GND) J127.2(GND) R22.1 R23.1 R27.2 R28.2 R29.2 R30.2 R62.2 R63.2 R68.1 R69.1
GND2: J76.2(GND) J77.2(GND) J78.2(GND) J79.2(GND) J80.2(GND) J81.2(GND) J82.2(GND) J83.2(GND) J84.2(GND) J85.2(GND) P2.A1(PRESENT) P2.A2(V12-A2) P2.A3(V12-A3) P2.A4(GND-A4) P2.A9(V3.3-A9) P2.A10(V3.3-A10) P2.A12(GND-A12) P2.A15(GND-A15) P2.A18(GND-A18) P2.A20(GND-A20) P2.A23(GND-A23) P2.A24(GND-A24) P2.A27(GND-A27) P2.A28(GND-A28) P2.A31(GND-A31) P2.B1(V12-B1) P2.B2(V12-B2) P2.B3(V12-B3) P2.B4(GND-B4) P2.B7(GND-B7) P2.B9(JTAG-B9) P2.B10(V3.3-B10) P2.B13(GND-B13) P2.B16(GND-B16) P2.B18(GND-B18) P2.B21(GND-B21) P2.B22(GND-B22) P2.B25(GND-B25) P2.B26(GND-B26) P2.B29(GND-B29) P2.B32(GND-B32) R32.1 R33.1 R34.1 R35.1 R36.1 R37.1 R38.2 R39.2 R40.2 R41.2 R42.2 R43.2
GND3: J94.2(GND) J95.2(GND) J96.2(GND) J97.2(GND) J98.2(GND) J99.2(GND) J100.2(GND) J101.2(GND) J102.2(GND) J103.2(GND) P1.A1(PRESENT) P1.A2(V12-A2) P1.A3(V12-A3) P1.A4(GND-A4) P1.A9(V3.3-A9) P1.A10(V3.3-A10) P1.A12(GND-A12) P1.A15(GND-A15) P1.A18(GND-A18) P1.A20(GND-A20) P1.A23(GND-A23) P1.A24(GND-A24) P1.A27(GND-A27) P1.A28(GND-A28) P1.A31(GND-A31) P1.B1(V12-B1) P1.B2(V12-B2) P1.B3(V12-B3) P1.B4(GND-B4) P1.B7(GND-B7) P1.B9(JTAG-B9) P1.B10(V3.3-B10) P1.B13(GND-B13) P1.B16(GND-B16) P1.B18(GND-B18) P1.B21(GND-B21) P1.B22(GND-B22) P1.B25(GND-B25) P1.B26(GND-B26) P1.B29(GND-B29) P1.B32(GND-B32) R44.1 R45.1 R46.1 R47.1 R48.1 R49.1 R50.2 R51.2 R52.2 R53.2 R54.2 R55.2
CLKREQ-GF1: C35.1 P1.B12(CLKREQ)
CLKREQ-GF2: C29.1 P2.B12(CLKREQ)
FACE2FACE: J106.1(SIGNAL) J112.1(SIGNAL)
FACE2FACE_TH: J118.1(SIGNAL) J124.1(SIGNAL)
LOAD: J105.1(SIGNAL) R66.2 R67.2
LOAD_TH_TH: J117.1(SIGNAL) R68.2 R69.2
PRESENT1-GF1: C38.1 P1.B31(PRESENT-B31)
PRESENT1-GF2: C32.1 P2.B31(PRESENT-B31)
PRESENT-GF1: C36.1 P1.B17(PRESENT-B17)
PRESENT-GF2: C30.1 P2.B17(PRESENT-B17)
PRIMARY_THRU: J104.1(SIGNAL) J111.1(SIGNAL)
PRIMARY_THRU_TH: J116.1(SIGNAL) J123.1(SIGNAL)
PWRBRK-GF1: C37.1 P1.B30(PWRBRK)
PWRBRK-GF2: C31.1 P2.B30(PWRBRK)
REFCLK-SMT_N: J66.A13(REFCLK-A13) R64.1
REFCLK-SMT_P: J66.A14(REFCLK-A14) R65.1
REFCLK-TH_N: J44.A13(REFCLK-A13) R62.1
REFCLK-TH_P: J44.A14(REFCLK-A14) R63.1
RSVD1-GF1: C34.2 P1.A32(RSVD-A32)
RSVD1-GF2: C28.2 P2.A32(RSVD-A32)
RSVD-GF1: C33.2 P1.A19(RSVD-A19)
RSVD-GF2: C27.2 P2.A19(RSVD-A19)
RX0-GF1_N: J100.1(SIGNAL) P1.A16(RX-A16)
RX0-GF1_P: J101.1(SIGNAL) P1.A17(RX-A17)
RX0-GF2_N: J82.1(SIGNAL) P2.A16(RX-A16)
RX0-GF2_P: J83.1(SIGNAL) P2.A17(RX-A17)
RX0-SMT_N: J56.1(SIGNAL) J66.A16(RX-A16)
RX0-SMT_P: J66.A17(RX-A17) J86.1(SIGNAL)
RX0-TH_N: J20.1(SIGNAL) J44.A16(RX-A16)
RX0-TH_P: J44.A17(RX-A17) J67.1(SIGNAL)
RX1-GF1_N: J102.1(SIGNAL) P1.A21(RX-A21)
RX1-GF1_P: J103.1(SIGNAL) P1.A22(RX-A22)
RX1-GF2_N: J84.1(SIGNAL) P2.A21(RX-A21)
RX1-GF2_P: J85.1(SIGNAL) P2.A22(RX-A22)
RX1-SMT_N: J66.A21(RX-A21) J87.1(SIGNAL)
RX1-SMT_P: J66.A22(RX-A22) J88.1(SIGNAL)
RX1-TH_N: J44.A21(RX-A21) J68.1(SIGNAL)
RX1-TH_P: J44.A22(RX-A22) J69.1(SIGNAL)
RX2-GF1_N: P1.A25(RX-A25) R52.1
RX2-GF1_P: P1.A26(RX-A26) R51.1
RX2-GF2_N: P2.A25(RX-A25) R40.1
RX2-GF2_P: P2.A26(RX-A26) R39.1
RX2-SMT_N: J66.A25(RX-A25) R59.1
RX2-SMT_P: J66.A26(RX-A26) R58.1
RX2-TH_N: J44.A25(RX-A25) R28.1
RX2-TH_P: J44.A26(RX-A26) R27.1
RX3-GF1_N: P1.A29(RX-A29) R53.1
RX3-GF1_P: P1.A30(RX-A30) R54.1
RX3-GF2_N: P2.A29(RX-A29) R41.1
RX3-GF2_P: P2.A30(RX-A30) R42.1
RX3-SMT_N: J66.A29(RX-A29) R60.1
RX3-SMT_P: J66.A30(RX-A30) R61.1
RX3-TH_N: J44.A29(RX-A29) R29.1
RX3-TH_P: J44.A30(RX-A30) R30.1
SECONDARY1: J108.1(SIGNAL) J113.1(SIGNAL)
SECONDARY1_TH: J120.1(SIGNAL) J125.1(SIGNAL)
SECONDARY2: J109.1(SIGNAL) J114.1(SIGNAL)
SECONDARY2_TH: J121.1(SIGNAL) J126.1(SIGNAL)
SECONDARY3: J110.1(SIGNAL) J115.1(SIGNAL)
SECONDARY3_TH: J122.1(SIGNAL) J127.1(SIGNAL)
TX0-GF1_N: J94.1(SIGNAL) P1.B14(TX-B14)
TX0-GF1_P: J95.1(SIGNAL) P1.B15(TX-B15)
TX0-GF2_N: J76.1(SIGNAL) P2.B14(TX-B14)
TX0-GF2_P: J77.1(SIGNAL) P2.B15(TX-B15)
TX0-SMT_N: J60.1(SIGNAL) J66.B14(TX-B14)
TX0-SMT_P: J66.B15(TX-B15) J89.1(SIGNAL)
TX0-TH_N: J44.B14(TX-B14) J70.1(SIGNAL)
TX0-TH_P: J44.B15(TX-B15) J71.1(SIGNAL)
TX1-GF1_N: J96.1(SIGNAL) P1.B19(TX-B19)
TX1-GF1_P: J97.1(SIGNAL) P1.B20(TX-B20)
TX1-GF2_N: J78.1(SIGNAL) P2.B19(TX-B19)
TX1-GF2_P: J79.1(SIGNAL) P2.B20(TX-B20)
TX1-SMT_N: J66.B19(TX-B19) J90.1(SIGNAL)
TX1-SMT_P: J66.B20(TX-B20) J91.1(SIGNAL)
TX1-TH_N: J44.B19(TX-B19) J72.1(SIGNAL)
TX1-TH_P: J44.B20(TX-B20) J73.1(SIGNAL)
TX2-GF1_N: J98.1(SIGNAL) P1.B23(TX-B23)
TX2-GF1_P: J99.1(SIGNAL) P1.B24(TX-B24)
TX2-GF2_N: J80.1(SIGNAL) P2.B23(TX-B23)
TX2-GF2_P: J81.1(SIGNAL) P2.B24(TX-B24)
TX2-SMT_N: J66.B23(TX-B23) J92.1(SIGNAL)
TX2-SMT_P: J66.B24(TX-B24) J93.1(SIGNAL)
TX2-TH_N: J44.B23(TX-B23) J74.1(SIGNAL)
TX2-TH_P: J44.B24(TX-B24) J75.1(SIGNAL)
TX3-GF1_N: P1.B27(TX-B27) R46.2
TX3-GF1_P: P1.B28(TX-B28) R47.2
TX3-GF2_N: P2.B27(TX-B27) R34.2
TX3-GF2_P: P2.B28(TX-B28) R35.2
TX3-SMT_N: J66.B27(TX-B27) R56.2
TX3-SMT_P: J66.B28(TX-B28) R57.2
TX3-TH_N: J44.B27(TX-B27) R22.2
TX3-TH_P: J44.B28(TX-B28) R23.2
N295225: C32.2 R37.2
N295261: C31.2 R36.2
N295961: C27.1 R38.1
N295971: C30.2 R33.2
N296497: C29.2 R32.2
N311833: C38.2 R49.2
N311853: C37.2 R48.2
N312429: C33.1 R50.1
N312439: C36.2 R45.2
N312937: C35.2 R44.2
N2956010: C28.1 R43.1
N3120750: C34.1 R55.1

Pads without a net: J44 A5 A6 A7 A8 A11 A19 A32 B5 B6 B8 B11 B12 B17 B30 B31; J66 A5 A6 A7 A8 A11 A19 A32 B5 B6 B8 B11 B12 B17 B30 B31; NOREF#26 1 2 3 4 5 6 7 8; NOREF#29 1 2 3 4 5 6 7 8; NOREF#33 1 2 3 4 5 6 7 8; NOREF#36 1 2 3 4 5 6 7 8; NOREF#37 1 2 3 4 5 6 7 8; NOREF#39 1 2 3 4 5 6 7 8; NOREF#55 1 2 3 4 5 6 7 8; NOREF#67 1 2 3 4 5 6 7 8; NOREF#72 1 2 3 4 5 6 7 8; NOREF#87 1 2 3 4 5 6 7 8; NOREF#95 1 2 3 4 5 6 7 8; NOREF#96 1 2 3 4 5 6 7 8; NOREF#99 1 2 3 4 5 6 7 8; NOREF#102 1 2 3 4 5 6 7 8; NOREF#113 1 2 3 4 5 6 7 8; NOREF#115 1 2 3 4 5 6 7 8; NOREF#118 1 2 3 4 5 6 7 8; NOREF#121 1 2 3 4 5 6 7 8; P1 A5 A6 A7 A8 A11 A13 A14 B5 B6 B8 B11; P2 A5 A6 A7 A8 A11 A13 A14 B5 B6 B8 B11

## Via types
v1: diameter 0.508, hole 0.254, TOP to BOTTOM, 480 vias
v2: diameter 0.457, hole 0.254, TOP to BOTTOM, 192 vias

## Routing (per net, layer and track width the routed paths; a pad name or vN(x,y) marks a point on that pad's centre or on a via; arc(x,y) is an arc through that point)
GND: length 174.8
  TOP w0.198: v1(65.75,208.32) J107.1
  TOP w0.259: R65.2 70.41,358.14 v1(70.46,358.19) ; v1(70.46,359.21) 70.41,359.16 R64.2 ; R57.1 v1(55.14,344.17) ; v1(70.43,342.16) 70.41,342.14 R61.2 ; v1(70.43,343.18) 70.41,343.15 R60.2 ; R58.2 v1(70.43,346.08) ; R66.1 v1(63.12,248.03) ; R67.1 v1(63.12,244.73) ; R56.1 v1(55.14,345.19) ; R59.2 v1(70.43,347.09)
  TOP w0.508: v1(67.7,360.14) J66.A12 v1(65.09,360.14) ; v1(67.7,365.14) J66.A9 v1(65.09,365.14) ; v1(67.7,371.14) J66.A3 v1(65.09,371.14) ; v1(65.09,372.14) J66.A2 v1(67.7,372.14) ; v1(60.5,343.14) J66.B29 v1(57.89,343.14) ; v1(60.5,372.14) J66.B2 v1(57.89,372.14) ; v1(67.7,345.14) J66.A27 v1(65.09,345.14) ; v1(60.5,365.14) J66.B9 v1(57.89,365.14) ; v1(67.7,349.14) J66.A23 v1(65.09,349.14) ; v1(60.5,371.14) J66.B3 v1(57.89,371.14) ; v1(57.89,350.14) J66.B22 v1(60.5,350.14) ; v1(65.09,352.14) J66.A20 v1(67.7,352.14) ; v1(60.5,351.14) J66.B21 v1(57.89,351.14) ; v1(60.5,359.14) J66.B13 v1(57.89,359.14) ; v1(60.5,364.14) J66.B10 v1(57.89,364.14) ; v1(57.89,370.14) J66.B4 v1(60.5,370.14) ; v1(67.7,370.14) J66.A4 v1(65.09,370.14) ; v1(60.5,356.14) J66.B16 v1(57.89,356.14) ; v1(65.09,348.14) J66.A24 v1(67.7,348.14) ; v1(67.7,354.14) J66.A18 v1(65.09,354.14) ; v1(67.7,341.14) J66.A31 v1(65.09,341.14) ; v1(57.89,347.14) J66.B25 v1(60.5,347.14) ; v1(57.89,367.14) J66.B7 v1(60.5,367.14) ; v1(67.7,364.14) J66.A10 v1(65.09,364.14) ; v1(67.7,373.14) J66.A1 v1(65.09,373.14) ; v1(60.5,346.14) J66.B26 v1(57.89,346.14) ; v1(65.09,357.14) J66.A15 v1(67.7,357.14) ; v1(60.5,373.14) J66.B1 v1(57.89,373.14) ; v1(67.7,344.14) J66.A28 v1(65.09,344.14) ; v1(57.89,354.14) J66.B18 v1(60.5,354.14) ; v1(60.5,340.14) J66.B32 v1(57.89,340.14)
  L2 w0.381: 17.39,246.08 J105.2 17.39,246.75 ; 106.82,366.03 J86.2 106.82,366.7 ; 18.67,144.48 J110.2 18.67,145.15 ; 13.72,347.55 J91.2 13.72,346.87 ; 97.77,328.06 J88.2 97.77,327.38 ; 35.16,227.7 J112.2 35.16,227.03 ; 110.46,145.15 J115.2 110.46,144.48 ; 18.67,188.63 J108.2 18.67,189.3 ; 16.66,227.03 J106.2 16.66,227.7 ; 48.6,389.67 J60.2 47.92,389.67 ; 103.74,346.08 J87.2 103.74,346.75 ; 19.03,208.65 J107.2 19.03,207.98 ; 104.68,188.63 J113.2 104.68,189.3 ; 25.32,362.23 J90.2 25.32,361.55 ; 16.97,265.13 J104.2 16.97,265.8 ; 92.16,381.92 J56.2 92.16,381.24 ; 20.89,328.35 J92.2 20.89,329.02 ; 18.67,160.69 J109.2 18.67,161.36 ; 109.26,161.5 J114.2 109.26,160.83 ; 29.13,379.19 J89.2 29.13,379.86 ; 106.78,265.13 J111.2 106.78,265.8 ; 37.81,315.34 J93.2 38.48,315.34
  L3 w0.381: 97.77,327.38 J88.2 97.77,328.06 ; 110.46,145.15 J115.2 110.46,144.48 ; 37.81,315.34 J93.2 38.48,315.34 ; 16.97,265.8 J104.2 16.97,265.13 ; 18.67,144.48 J110.2 18.67,145.15 ; 35.16,227.03 J112.2 35.16,227.7 ; 17.39,246.08 J105.2 17.39,246.75 ; 109.26,160.83 J114.2 109.26,161.5 ; 16.66,227.03 J106.2 16.66,227.7 ; 104.68,188.63 J113.2 104.68,189.3 ; 47.92,389.67 J60.2 48.6,389.67 ; 18.67,189.3 J108.2 18.67,188.63 ; 18.67,160.69 J109.2 18.67,161.36 ; 106.82,366.03 J86.2 106.82,366.7 ; 103.74,346.75 J87.2 103.74,346.08 ; 106.78,265.8 J111.2 106.78,265.13 ; 20.89,329.02 J92.2 20.89,328.35 ; 19.03,208.65 J107.2 19.03,207.98 ; 92.16,381.24 J56.2 92.16,381.92 ; 29.13,379.19 J89.2 29.13,379.86 ; 25.32,362.23 J90.2 25.32,361.55 ; 13.72,346.87 J91.2 13.72,347.55
  vias: v2(14.26,347.67) v2(14.26,346.75) v2(14.72,347.87) v2(14.72,346.55) v2(15.18,347.67) v2(15.18,346.75) v2(17.2,227.83) v2(17.2,226.91) v2(17.5,265.93) v2(17.5,265.01) v2(17.66,228.03) v2(17.66,226.71) v2(17.96,266.13) v2(17.96,264.81) v2(17.93,246.88) v2(17.93,245.96) v2(18.12,227.83) v2(18.12,226.91) v2(18.39,247.08) v2(18.39,245.76) v2(18.42,265.93) v2(18.42,265.01) v2(18.84,246.88) v2(18.84,245.96) v2(19.2,189.42) v2(19.2,188.5) v2(19.2,161.48) v2(19.2,160.56) v2(19.2,145.28) v2(19.2,144.36) v2(19.57,208.78) v2(19.57,207.86) v2(19.66,189.62) v2(19.66,188.3) v2(19.66,161.68) v2(19.66,160.36) v2(19.66,145.48) v2(19.66,144.16) v2(20.03,208.98) v2(20.03,207.66) v2(20.12,189.42) v2(20.12,188.5) v2(20.12,161.48) v2(20.12,160.56) v2(20.12,145.28) v2(20.12,144.36) v2(20.48,208.78) v2(20.48,207.86) v2(21.43,329.14) v2(21.43,328.23) v2(21.89,329.35) v2(21.89,328.02) v2(22.34,329.14) v2(22.34,328.23) v2(25.86,362.35) v2(25.86,361.43) v2(26.32,362.55) v2(26.32,361.23) v2(26.77,362.35) v2(26.77,361.43) v2(29.66,379.98) v2(29.66,379.07) v2(30.12,380.19) v2(30.12,378.86) v2(30.58,379.98) v2(30.58,379.07) v2(33.71,227.83) v2(33.71,226.91) v2(34.17,228.03) v2(34.17,226.71) v2(34.63,227.83) v2(34.63,226.91) v2(37.49,316.34) v2(37.69,316.79) v2(37.69,315.88) v2(38.61,316.79) v2(38.61,315.88) v2(38.81,316.34) v2(47.6,388.67) v2(47.8,389.13) v2(47.8,388.21) v2(48.72,389.13) v2(48.72,388.21) v2(48.92,388.67) v2(90.7,382.04) v2(90.7,381.12) v2(91.16,382.24) v2(91.16,380.92) v2(91.62,382.04) v2(91.62,381.12) v2(96.32,328.18) v2(96.32,327.26) v2(96.78,328.38) v2(96.78,327.06) v2(97.24,328.18) v2(97.24,327.26) v2(102.29,346.88) v2(102.29,345.96) v2(102.75,347.08) v2(102.75,345.76) v2(103.21,346.88) v2(103.21,345.96) v2(103.23,189.42) v2(103.23,188.51) v2(103.69,189.63) v2(103.69,188.3) v2(104.15,189.42) v2(104.15,188.51) v2(105.36,366.83) v2(105.36,365.91) v2(105.33,265.93) v2(105.33,265.01) v2(105.78,266.13) v2(105.78,264.81) v2(105.82,367.03) v2(105.82,365.71) v2(106.28,366.83) v2(106.28,365.91) v2(106.24,265.93) v2(106.24,265.01) v2(107.81,161.62) v2(107.81,160.71) v2(108.27,161.83) v2(108.27,160.5) v2(108.73,161.62) v2(108.73,160.71) v2(109.01,145.28) v2(109.01,144.36) v2(109.46,145.48) v2(109.46,144.16) v2(109.92,145.28) v2(109.92,144.36)
GND1: length 327.3
  L2 w0.381: 364.25,145.17 J127.2 ; J127.2 364.96,145.17 ; J127.2 364.96,144.46 ; J127.2 364.25,144.46 ; 315.71,367.89 J44.B7 ; J44.B7 316.78,366.82 ; J44.B7 316.78,367.89 ; J44.B7 315.71,366.82 ; J44.A27 319.28,344.82 ; J44.A27 318.21,345.89 ; J44.A27 319.28,345.89 ; J44.A27 318.21,344.82 ; J44.A9 319.28,365.89 ; J44.A9 318.21,364.82 ; J44.A9 318.21,365.89 ; J44.A9 319.28,364.82 ; 270.16,227.72 J118.2 ; J118.2 270.87,227.72 ; J118.2 270.87,227.01 ; J118.2 270.16,227.01 ; 320.21,364.89 J44.A10 ; J44.A10 321.28,364.89 ; J44.A10 321.28,363.82 ; J44.A10 320.21,363.82 ; J44.B21 316.78,350.82 ; J44.B21 316.78,351.89 ; J44.B21 315.71,350.82 ; J44.B21 315.71,351.89 ; 320.21,371.82 J44.A2 ; J44.A2 321.28,371.82 ; J44.A2 320.21,372.89 ; J44.A2 321.28,372.89 ; J71.2 283.34,379.17 ; J71.2 282.63,379.88 ; J71.2 283.34,379.88 ; J71.2 282.63,379.17 ; J44.A1 319.28,372.82 ; J44.A1 318.21,372.82 ; J44.A1 318.21,373.89 ; J44.A1 319.28,373.89 ; 313.71,371.82 J44.B2 ; J44.B2 314.78,371.82 ; J44.B2 313.71,372.89 ; J44.B2 314.78,372.89 ; J116.2 271.18,265.82 ; J116.2 270.47,265.11 ; J116.2 271.18,265.11 ; J116.2 270.47,265.82 ; J70.2 302.61,390.17 ; J70.2 302.61,389.46 ; J70.2 301.91,389.46 ; J70.2 301.91,390.17 ; J121.2 272.88,161.38 ; J121.2 272.17,161.38 ; J121.2 272.88,160.67 ; J121.2 272.17,160.67 ; J44.B9 316.78,364.82 ; J44.B9 315.71,365.89 ; J44.B9 316.78,365.89 ; J44.B9 315.71,364.82 ; J126.2 363.76,161.52 ; J126.2 363.05,161.52 ; J126.2 363.76,160.81 ; J126.2 363.05,160.81 ; J44.A3 319.28,371.89 ; J44.A3 318.21,370.82 ; J44.A3 319.28,370.82 ; J44.A3 318.21,371.89 ; 320.21,344.89 J44.A28 ; J44.A28 321.28,343.82 ; J44.A28 321.28,344.89 ; J44.A28 320.21,343.82 ; J44.A20 321.28,351.82 ; J44.A20 321.28,352.89 ; J44.A20 320.21,352.89 ; J44.A20 320.21,351.82 ; 320.21,369.82 J44.A4 ; J44.A4 320.21,370.89 ; J44.A4 321.28,370.89 ; J44.A4 321.28,369.82 ; J44.A23 319.28,349.89 ; J44.A23 318.21,349.89 ; J44.A23 318.21,348.82 ; J44.A23 319.28,348.82 ; 272.17,189.32 J120.2 ; J120.2 272.17,188.61 ; J120.2 272.88,189.32 ; J120.2 272.88,188.61 ; 315.71,358.82 J44.B13 ; J44.B13 316.78,359.89 ; J44.B13 315.71,359.89 ; J44.B13 316.78,358.82 ; J119.2 273.24,208.67 ; J119.2 273.24,207.96 ; J119.2 272.53,208.67 ; J119.2 272.53,207.96 ; 313.71,356.89 J44.B16 ; J44.B16 313.71,355.82 ; J44.B16 314.78,355.82 ; J44.B16 314.78,356.89 ; J44.A31 319.28,340.82 ; J44.A31 318.21,341.89 ; J44.A31 318.21,340.82 ; J44.A31 319.28,341.89 ; J69.2 352.27,327.37 ; J69.2 352.27,328.08 ; J69.2 351.56,327.37 ; J69.2 351.56,328.08 ; J44.B25 316.78,346.82 ; J44.B25 315.71,346.82 ; J44.B25 315.71,347.89 ; J44.B25 316.78,347.89 ; J44.A24 321.28,348.89 ; J44.A24 321.28,347.82 ; J44.A24 320.21,347.82 ; J44.A24 320.21,348.89 ; J44.B26 314.78,346.89 ; J44.B26 313.71,345.82 ; J44.B26 313.71,346.89 ; J44.B26 314.78,345.82 ; J44.B4 314.78,369.82 ; J44.B4 313.71,369.82 ; J44.B4 313.71,370.89 ; J44.B4 314.78,370.89 ; 318.21,356.82 J44.A15 ; J44.A15 319.28,356.82 ; J44.A15 318.21,357.89 ; J44.A15 319.28,357.89 ; 313.71,353.82 J44.B18 ; J44.B18 313.71,354.89 ; J44.B18 314.78,354.89 ; J44.B18 314.78,353.82 ; J124.2 289.66,227.01 ; J124.2 289.66,227.72 ; J124.2 288.95,227.01 ; J124.2 288.95,227.72 ; J75.2 292.5,314.84 ; J75.2 291.79,315.55 ; J75.2 291.79,314.84 ; J75.2 292.5,315.55 ; J44.B29 316.78,342.82 ; J44.B29 315.71,343.89 ; J44.B29 315.71,342.82 ; J44.B29 316.78,343.89 ; 313.71,364.89 J44.B10 ; J44.B10 313.71,363.82 ; J44.B10 314.78,364.89 ; J44.B10 314.78,363.82 ; 320.21,354.89 J44.A18 ; J44.A18 321.28,353.82 ; J44.A18 320.21,353.82 ; J44.A18 321.28,354.89 ; J72.2 279.53,362.24 ; J72.2 278.82,362.24 ; J72.2 279.53,361.53 ; J72.2 278.82,361.53 ; 313.71,340.89 J44.B32 ; J44.B32 313.71,339.82 ; J44.B32 314.78,339.82 ; J44.B32 314.78,340.89 ; 358.47,188.61 J125.2 ; J125.2 359.18,189.32 ; J125.2 358.47,189.32 ; J125.2 359.18,188.61 ; 315.71,373.89 J44.B1 ; J44.B1 316.78,373.89 ; J44.B1 316.78,372.82 ; J44.B1 315.71,372.82 ; 313.71,349.82 J44.B22 ; J44.B22 313.71,350.89 ; J44.B22 314.78,350.89 ; J44.B22 314.78,349.82 ; 270.43,346.85 J73.2 ; J73.2 271.14,346.85 ; J73.2 271.14,347.56 ; J73.2 270.43,347.56 ; J67.2 361.31,366.72 ; J67.2 360.61,366.72 ; J67.2 360.61,366.01 ; J67.2 361.31,366.01 ; J123.2 361.28,265.82 ; J123.2 360.57,265.11 ; J123.2 361.28,265.11 ; J123.2 360.57,265.82 ; 270.89,246.06 J117.2 ; J117.2 270.89,246.77 ; J117.2 271.6,246.06 ; J117.2 271.6,246.77 ; J122.2 272.88,144.46 ; J122.2 272.88,145.17 ; J122.2 272.17,145.17 ; J122.2 272.17,144.46 ; 345.95,381.23 J20.2 ; J20.2 346.65,381.94 ; J20.2 346.65,381.23 ; J20.2 345.95,381.94 ; J44.A12 321.28,359.82 ; J44.A12 321.28,360.89 ; J44.A12 320.21,359.82 ; J44.A12 320.21,360.89 ; 276.93,331.58 J74.2 ; J74.2 277.64,331.58 ; J74.2 277.64,330.87 ; J74.2 276.93,330.87 ; J44.B3 316.78,370.82 ; J44.B3 316.78,371.89 ; J44.B3 315.71,370.82 ; J44.B3 315.71,371.89 ; 357.53,346.77 J68.2 ; J68.2 357.53,346.06 ; J68.2 358.24,346.77 ; J68.2 358.24,346.06
  L3 w0.381: J44.B10 314.78,364.89 ; J44.B10 313.71,363.82 ; J44.B10 314.78,363.82 ; J44.B10 313.71,364.89 ; J44.B16 314.78,356.89 ; J44.B16 313.71,355.82 ; J44.B16 314.78,355.82 ; J44.B16 313.71,356.89 ; J44.B1 316.78,373.89 ; J44.B1 315.71,372.82 ; J44.B1 315.71,373.89 ; J44.B1 316.78,372.82 ; 272.53,208.67 J119.2 ; J119.2 273.24,208.67 ; J119.2 273.24,207.96 ; J119.2 272.53,207.96 ; 315.71,347.89 J44.B25 ; J44.B25 315.71,346.82 ; J44.B25 316.78,346.82 ; J44.B25 316.78,347.89 ; J44.A15 319.28,357.89 ; J44.A15 318.21,356.82 ; J44.A15 319.28,356.82 ; J44.A15 318.21,357.89 ; 320.21,343.82 J44.A28 ; J44.A28 320.21,344.89 ; J44.A28 321.28,343.82 ; J44.A28 321.28,344.89 ; 291.79,315.55 J75.2 ; J75.2 292.5,314.84 ; J75.2 292.5,315.55 ; J75.2 291.79,314.84 ; 313.71,350.89 J44.B22 ; J44.B22 314.78,350.89 ; J44.B22 314.78,349.82 ; J44.B22 313.71,349.82 ; J116.2 271.18,265.11 ; J116.2 270.47,265.11 ; J116.2 270.47,265.82 ; J116.2 271.18,265.82 ; J44.A20 321.28,352.89 ; J44.A20 321.28,351.82 ; J44.A20 320.21,351.82 ; J44.A20 320.21,352.89 ; J44.A12 321.28,360.89 ; J44.A12 320.21,360.89 ; J44.A12 320.21,359.82 ; J44.A12 321.28,359.82 ; 315.71,351.89 J44.B21 ; J44.B21 316.78,351.89 ; J44.B21 315.71,350.82 ; J44.B21 316.78,350.82 ; 313.71,340.89 J44.B32 ; J44.B32 314.78,339.82 ; J44.B32 313.71,339.82 ; J44.B32 314.78,340.89 ; 272.17,144.46 J122.2 ; J122.2 272.88,144.46 ; J122.2 272.88,145.17 ; J122.2 272.17,145.17 ; J44.B9 316.78,365.89 ; J44.B9 315.71,365.89 ; J44.B9 316.78,364.82 ; J44.B9 315.71,364.82 ; J123.2 361.28,265.82 ; J123.2 360.57,265.82 ; J123.2 361.28,265.11 ; J123.2 360.57,265.11 ; 315.71,359.89 J44.B13 ; J44.B13 316.78,359.89 ; J44.B13 316.78,358.82 ; J44.B13 315.71,358.82 ; J68.2 358.24,346.77 ; J68.2 358.24,346.06 ; J68.2 357.53,346.77 ; J68.2 357.53,346.06 ; J72.2 279.53,361.53 ; J72.2 279.53,362.24 ; J72.2 278.82,362.24 ; J72.2 278.82,361.53 ; 345.95,381.94 J20.2 ; J20.2 345.95,381.23 ; J20.2 346.65,381.23 ; J20.2 346.65,381.94 ; 313.71,370.89 J44.B4 ; J44.B4 314.78,369.82 ; J44.B4 314.78,370.89 ; J44.B4 313.71,369.82 ; J74.2 277.64,331.58 ; J74.2 276.93,331.58 ; J74.2 277.64,330.87 ; J74.2 276.93,330.87 ; J118.2 270.87,227.01 ; J118.2 270.16,227.01 ; J118.2 270.87,227.72 ; J118.2 270.16,227.72 ; 318.21,372.82 J44.A1 ; J44.A1 319.28,372.82 ; J44.A1 318.21,373.89 ; J44.A1 319.28,373.89 ; 313.71,346.89 J44.B26 ; J44.B26 313.71,345.82 ; J44.B26 314.78,345.82 ; J44.B26 314.78,346.89 ; 272.17,189.32 J120.2 ; J120.2 272.17,188.61 ; J120.2 272.88,189.32 ; J120.2 272.88,188.61 ; 288.95,227.01 J124.2 ; J124.2 289.66,227.72 ; J124.2 288.95,227.72 ; J124.2 289.66,227.01 ; 313.71,354.89 J44.B18 ; J44.B18 313.71,353.82 ; J44.B18 314.78,353.82 ; J44.B18 314.78,354.89 ; J44.B29 316.78,342.82 ; J44.B29 315.71,342.82 ; J44.B29 315.71,343.89 ; J44.B29 316.78,343.89 ; J121.2 272.88,160.67 ; J121.2 272.88,161.38 ; J121.2 272.17,160.67 ; J121.2 272.17,161.38 ; 282.63,379.88 J71.2 ; J71.2 283.34,379.88 ; J71.2 282.63,379.17 ; J71.2 283.34,379.17 ; 358.47,189.32 J125.2 ; J125.2 359.18,188.61 ; J125.2 358.47,188.61 ; J125.2 359.18,189.32 ; 363.05,160.81 J126.2 ; J126.2 363.05,161.52 ; J126.2 363.76,160.81 ; J126.2 363.76,161.52 ; 315.71,366.82 J44.B7 ; J44.B7 316.78,367.89 ; J44.B7 316.78,366.82 ; J44.B7 315.71,367.89 ; J44.A3 319.28,371.89 ; J44.A3 318.21,370.82 ; J44.A3 318.21,371.89 ; J44.A3 319.28,370.82 ; 318.21,345.89 J44.A27 ; J44.A27 319.28,345.89 ; J44.A27 318.21,344.82 ; J44.A27 319.28,344.82 ; 320.21,354.89 J44.A18 ; J44.A18 321.28,354.89 ; J44.A18 321.28,353.82 ; J44.A18 320.21,353.82 ; 360.61,366.72 J67.2 ; J67.2 361.31,366.01 ; J67.2 360.61,366.01 ; J67.2 361.31,366.72 ; 351.56,328.08 J69.2 ; J69.2 352.27,328.08 ; J69.2 352.27,327.37 ; J69.2 351.56,327.37 ; 320.21,348.89 J44.A24 ; J44.A24 320.21,347.82 ; J44.A24 321.28,348.89 ; J44.A24 321.28,347.82 ; 270.43,347.56 J73.2 ; J73.2 271.14,346.85 ; J73.2 270.43,346.85 ; J73.2 271.14,347.56 ; 315.71,370.82 J44.B3 ; J44.B3 316.78,370.82 ; J44.B3 315.71,371.89 ; J44.B3 316.78,371.89 ; 364.25,144.46 J127.2 ; J127.2 364.96,144.46 ; J127.2 364.96,145.17 ; J127.2 364.25,145.17 ; 301.91,390.17 J70.2 ; J70.2 302.61,389.46 ; J70.2 301.91,389.46 ; J70.2 302.61,390.17 ; J44.A4 321.28,370.89 ; J44.A4 321.28,369.82 ; J44.A4 320.21,370.89 ; J44.A4 320.21,369.82 ; 320.21,372.89 J44.A2 ; J44.A2 320.21,371.82 ; J44.A2 321.28,372.89 ; J44.A2 321.28,371.82 ; 318.21,348.82 J44.A23 ; J44.A23 318.21,349.89 ; J44.A23 319.28,349.89 ; J44.A23 319.28,348.82 ; J44.A9 319.28,365.89 ; J44.A9 318.21,364.82 ; J44.A9 319.28,364.82 ; J44.A9 318.21,365.89 ; 318.21,340.82 J44.A31 ; J44.A31 318.21,341.89 ; J44.A31 319.28,340.82 ; J44.A31 319.28,341.89 ; J44.A10 321.28,364.89 ; J44.A10 320.21,364.89 ; J44.A10 320.21,363.82 ; J44.A10 321.28,363.82 ; J117.2 271.6,246.77 ; J117.2 271.6,246.06 ; J117.2 270.89,246.06 ; J117.2 270.89,246.77 ; J44.B2 314.78,371.82 ; J44.B2 313.71,371.82 ; J44.B2 313.71,372.89 ; J44.B2 314.78,372.89
  BOTTOM w0.198: J119.1 v1(319.75,208.32) ; R69.1 v1(317.12,244.73) ; R68.1 v1(317.12,248.03)
  BOTTOM w0.259: v1(326.8,358.42) 326.77,358.39 R63.2 ; R23.1 v1(308.23,344.42) ; R29.2 324.05,343.41 v1(324.08,343.43) ; v1(326.8,342.42) 326.77,342.39 R30.2 ; v1(326.8,346.35) 326.77,346.33 R27.2 ; R28.2 324.03,347.35 v1(324.05,347.37) ; R62.2 324.79,359.41 v1(324.82,359.44) ; R22.1 v1(310.39,345.44)
  vias: v1(270.85,228.18) v1(270.85,226.56) v1(271.11,348.02) v1(271.11,346.4) v1(271.15,266.28) v1(271.15,264.66) v1(271.57,247.23) v1(271.57,245.61) v1(271.63,228.51) v1(271.66,226.23) v1(271.9,348.35) v1(271.92,346.07) v1(271.94,266.61) v1(271.96,264.33) v1(272.36,247.56) v1(272.39,245.28) v1(272.47,228.18) v1(272.47,226.56) v1(272.73,348.02) v1(272.73,346.4) v1(272.78,266.28) v1(272.78,264.66) v1(272.85,189.78) v1(272.85,188.15) v1(272.85,161.84) v1(272.85,160.21) v1(272.85,145.63) v1(272.85,144.01) v1(273.2,247.23) v1(273.2,245.61) v1(273.23,228.18) v1(273.23,226.56) v1(273.21,209.13) v1(273.21,207.51) v1(273.5,348.02) v1(273.5,346.4) v1(273.54,266.28) v1(273.54,264.66) v1(273.64,190.1) v1(273.66,187.82) v1(273.64,162.16) v1(273.66,159.88) v1(273.64,145.96) v1(273.66,143.68) v1(273.96,247.23) v1(273.96,245.61) v1(273.99,228.18) v1(273.99,226.56) v1(274,209.46) v1(274.03,207.18) v1(274.26,348.02) v1(274.26,346.4) v1(274.3,266.28) v1(274.3,264.66) v1(274.48,189.78) v1(274.48,188.15) v1(274.48,161.84) v1(274.48,160.21) v1(274.48,145.63) v1(274.48,144.01) v1(274.72,247.23) v1(274.72,245.61) v1(274.84,209.13) v1(274.84,207.51) v1(275.24,189.78) v1(275.24,188.15) v1(275.24,161.84) v1(275.24,160.21) v1(275.24,145.63) v1(275.24,144.01) v1(275.6,209.13) v1(275.6,207.51) v1(276,189.78) v1(276,188.15) v1(276,161.84) v1(276,160.21) v1(276,145.63) v1(276,144.01) v1(276.36,209.13) v1(276.36,207.51) v1(277.61,332.04) v1(277.61,330.41) v1(278.4,332.37) v1(278.43,330.09) v1(279.24,332.04) v1(279.24,330.41) v1(279.5,362.7) v1(279.5,361.08) v1(280,332.04) v1(280,330.41) v1(280.29,363.03) v1(280.32,360.75) v1(280.76,332.04) v1(280.76,330.41) v1(281.13,362.7) v1(281.13,361.08) v1(281.89,362.7) v1(281.89,361.08) v1(282.65,362.7) v1(282.65,361.08) v1(283.31,380.34) v1(283.31,378.71) v1(284.1,380.67) v1(284.12,378.39) v1(284.94,380.34) v1(284.94,378.71) v1(285.7,380.34) v1(285.7,378.71) v1(285.83,228.18) v1(285.83,226.56) v1(286.46,380.34) v1(286.46,378.71) v1(286.59,228.18) v1(286.59,226.56) v1(287.36,228.18) v1(287.36,226.56) v1(288.17,228.51) v1(288.19,226.23) v1(288.98,228.18) v1(288.98,226.56) v1(291.01,316.31) v1(291.33,318.67) v1(291.33,317.91) v1(291.33,317.15) v1(291.33,315.52) v1(292.96,318.67) v1(292.96,317.91) v1(292.96,317.15) v1(292.96,315.52) v1(293.29,316.34) v1(301.12,388.67) v1(301.45,389.48) v1(301.45,387.86) v1(301.45,387.1) v1(301.45,386.33) v1(303.07,389.48) v1(303.07,387.86) v1(303.07,387.1) v1(303.07,386.33) v1(303.4,388.7) v1(313.45,360.81) v1(313.45,342.81) v1(315.05,359.89) v1(315.05,341.89) v1(315.45,355.81) v1(315.45,340.89) v1(317.05,354.89) v1(317.06,341.82) v1(317.95,359.81) v1(317.95,358.89) v1(317.95,353.81) v1(319.56,359.82) v1(319.55,352.89) v1(319.95,358.81) v1(319.95,357.89) v1(319.95,340.81) v1(321.55,357.89) v1(321.55,339.89) v1(342.82,382.39) v1(342.82,380.77) v1(343.58,382.39) v1(343.58,380.77) v1(344.35,382.39) v1(344.35,380.77) v1(345.16,382.72) v1(345.19,380.44) v1(345.97,382.39) v1(345.97,380.77) v1(348.44,328.53) v1(348.44,326.91) v1(349.2,328.53) v1(349.2,326.91) v1(349.96,328.53) v1(349.96,326.91) v1(350.78,328.86) v1(350.8,326.58) v1(351.59,328.53) v1(351.59,326.91) v1(354.41,347.23) v1(354.41,345.6) v1(355.17,347.23) v1(355.17,345.6) v1(355.35,189.78) v1(355.35,188.15) v1(355.93,347.23) v1(355.93,345.6) v1(356.11,189.78) v1(356.11,188.15) v1(356.75,347.56) v1(356.77,345.28) v1(356.87,189.78) v1(356.87,188.15) v1(357.48,367.18) v1(357.48,365.55) v1(357.45,266.28) v1(357.45,264.66) v1(357.56,347.23) v1(357.56,345.6) v1(357.69,190.1) v1(357.71,187.82) v1(358.24,367.18) v1(358.24,365.55) v1(358.21,266.28) v1(358.21,264.66) v1(358.5,189.78) v1(358.5,188.15) v1(358.97,266.28) v1(358.97,264.66) v1(359.01,367.18) v1(359.01,365.55) v1(359.78,266.61) v1(359.82,367.51) v1(359.85,365.23) v1(359.81,264.33) v1(359.93,161.98) v1(359.93,160.35) v1(360.6,266.28) v1(360.6,264.66) v1(360.63,367.18) v1(360.63,365.55) v1(360.69,161.98) v1(360.69,160.35) v1(361.13,145.63) v1(361.13,144.01) v1(361.46,161.98) v1(361.46,160.35) v1(361.89,145.63) v1(361.89,144.01) v1(362.27,162.31) v1(362.29,160.02) v1(362.65,145.63) v1(362.65,144.01) v1(363.08,161.98) v1(363.08,160.35) v1(363.46,145.96) v1(363.49,143.68) v1(364.28,145.63) v1(364.28,144.01)
GND2: length 97.5
  TOP w0.259: v1(313.69,13.72) R33.1 ; R35.1 v1(325.12,12.55) ; R36.1 v1(327.66,13.82) ; v1(324.1,12.55) R34.1 ; v1(309.25,13.69) R32.1 ; R37.1 v1(328.93,13.82)
  TOP w0.508: P2.B22 319.05,5.66 319.39,6.01 ; P2.B29 326.05,5.59 325.63,6.01 v1(325.55,6.01) ; P2.B13 310.05,5.62 310.44,6.01 v1(310.54,6.01) ; v1(298.54,6.01) 298.45,6.01 298.05,5.6 P2.A3 ; v1(305.55,6.01) 305.46,6.01 305.05,5.59 P2.A10 ; P2.B7 302.05,5.6 301.64,6.01 v1(301.55,6.01) ; 317.72,6.01 319.39,6.01 ; 317.72,6.01 318.05,5.68 P2.B21 ; 317.72,6.01 v1(317.54,6.01) ; 319.39,6.01 v1(319.54,6.01) ; 323.34,6.01 321.72,6.01 ; 323.34,6.01 323.05,5.71 P2.B26 ; 323.34,6.01 v1(323.55,6.01) ; 321.72,6.01 322.05,5.68 P2.B25 ; 321.72,6.01 v1(321.54,6.01) ; v1(297.55,6.01) 297.45,6.01 297.05,5.61 P2.A2 ; P2.A18 315.05,5.61 315.44,6.01 v1(315.54,6.01) ; v1(299.54,6.01) 299.44,6.01 299.05,5.61 P2.A4 ; P2.A1 296.05,5.6 296.45,6.01 v1(296.55,6.01) ; v1(312.55,6.01) 312.64,6.01 313.05,5.6 P2.B16 ; v1(303.54,6.01) 303.64,6.01 304.05,5.6 P2.A9 ; v1(328.54,6.01) 328.63,6.01 329.05,5.59 P2.B32
  BOTTOM w0.259: R38.2 v1(315.34,13.72) ; R43.2 v1(329.95,13.82) ; R42.2 v1(326.77,12.04) ; R39.2 v1(323.22,12.04) ; v1(325.83,12.04) 325.75,11.96 R41.2 ; R40.2 v1(322.2,12.04)
  BOTTOM w0.508: P2.A2 297.05,5.63 297.43,6.01 v1(297.55,6.01) ; P2.A28 325.05,5.79 325.26,6.01 ; v1(303.54,6.01) 303.83,6.01 ; 303.83,6.01 305.27,6.01 ; 303.83,6.01 304.05,5.79 P2.A9 ; v1(317.54,6.01) 317.46,6.01 317.05,5.59 P2.A20 ; P2.A4 299.05,5.63 299.43,6.01 v1(299.54,6.01) ; 325.26,6.01 323.84,6.01 ; 325.26,6.01 v1(325.55,6.01) ; 323.84,6.01 v1(323.55,6.01) ; 323.84,6.01 324.05,5.8 P2.A27 ; P2.A24 321.05,5.8 321.26,6.01 ; P2.A18 315.05,5.6 315.46,6.01 v1(315.54,6.01) ; P2.A15 312.05,5.6 312.46,6.01 v1(312.55,6.01) ; v1(328.54,6.01) 328.46,6.01 328.05,5.59 P2.A31 ; v1(319.54,6.01) 319.82,6.01 ; 319.82,6.01 320.05,5.78 P2.A23 ; 319.82,6.01 321.26,6.01 ; v1(298.54,6.01) 298.43,6.01 298.05,5.63 P2.A3 ; v1(309.55,6.01) 309.45,6.01 309.05,5.61 P2.A12 ; P2.A10 305.05,5.78 305.27,6.01 ; 305.27,6.01 v1(305.55,6.01) ; 321.26,6.01 v1(321.54,6.01) ; v1(296.55,6.01) 296.43,6.01 296.05,5.63 P2.A1
  vias: v1(277.46,15.46) v1(277.46,13.83) v1(278.27,15.79) v1(278.24,13.51) v1(279.08,15.46) v1(279.08,13.83) v1(279.84,15.46) v1(279.84,13.83) v1(280.61,15.46) v1(280.61,13.83) v1(286.2,32.58) v1(286.53,33.37) v1(286.53,31.74) v1(286.53,30.98) v1(286.53,30.22) v1(288.15,33.37) v1(288.15,31.74) v1(288.15,30.98) v1(288.15,30.22) v1(288.48,32.55) v1(297.05,41.69) v1(297.38,42.5) v1(297.38,40.87) v1(297.38,40.11) v1(297.38,39.35) v1(299.01,42.5) v1(299.01,40.87) v1(299.01,40.11) v1(299.01,39.35) v1(299.34,41.71) v1(308.51,43.98) v1(308.84,44.77) v1(308.84,43.14) v1(308.84,42.38) v1(308.84,41.62) v1(310.46,44.77) v1(310.46,43.14) v1(310.46,42.38) v1(310.46,41.62) v1(310.79,43.95) v1(316.95,31.94) v1(316.95,30.32) v1(317.74,32.27) v1(317.77,29.99) v1(318.58,31.94) v1(318.58,30.32) v1(319.34,31.94) v1(319.34,30.32) v1(320.1,31.94) v1(320.1,30.32) v1(328.29,46.22) v1(328.61,47.01) v1(328.61,45.38) v1(328.61,44.62) v1(328.61,43.86) v1(330.24,47.01) v1(330.24,45.38) v1(330.24,44.62) v1(330.24,43.86) v1(330.57,46.19) v1(336.88,36.34) v1(337.21,37.15) v1(337.21,35.52) v1(337.21,34.76) v1(337.21,34) v1(338.83,37.15) v1(338.83,35.52) v1(338.83,34.76) v1(338.83,34) v1(339.16,36.36) v1(346.75,22.84) v1(347.08,23.65) v1(347.08,22.02) v1(347.08,21.26) v1(347.08,20.5) v1(347.23,32.82) v1(347.24,31.19) v1(347.99,32.82) v1(348,31.2) v1(348.75,32.83) v1(348.76,31.2) v1(348.71,23.65) v1(348.71,22.02) v1(348.71,21.26) v1(348.71,20.5) v1(349.03,22.86) v1(349.59,33.16) v1(349.57,30.88) v1(350.38,32.84) v1(350.39,31.21) v1(355.6,15.46) v1(355.6,13.83) v1(356.36,15.46) v1(356.36,13.83) v1(357.12,15.46) v1(357.12,13.83) v1(357.96,15.79) v1(357.93,13.51) v1(358.75,15.46) v1(358.75,13.83)
